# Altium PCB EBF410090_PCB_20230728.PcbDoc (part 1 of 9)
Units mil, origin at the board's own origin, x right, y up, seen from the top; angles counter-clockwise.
Board outline 5393.69 x 3858.26 mil, 6 copper layers (TOP, GND02, ART03, ART04, PWR05, BOTTOM), stack 47.2 mil thick; 570 components, 437 nets, 2015 pads, 1260 vias.
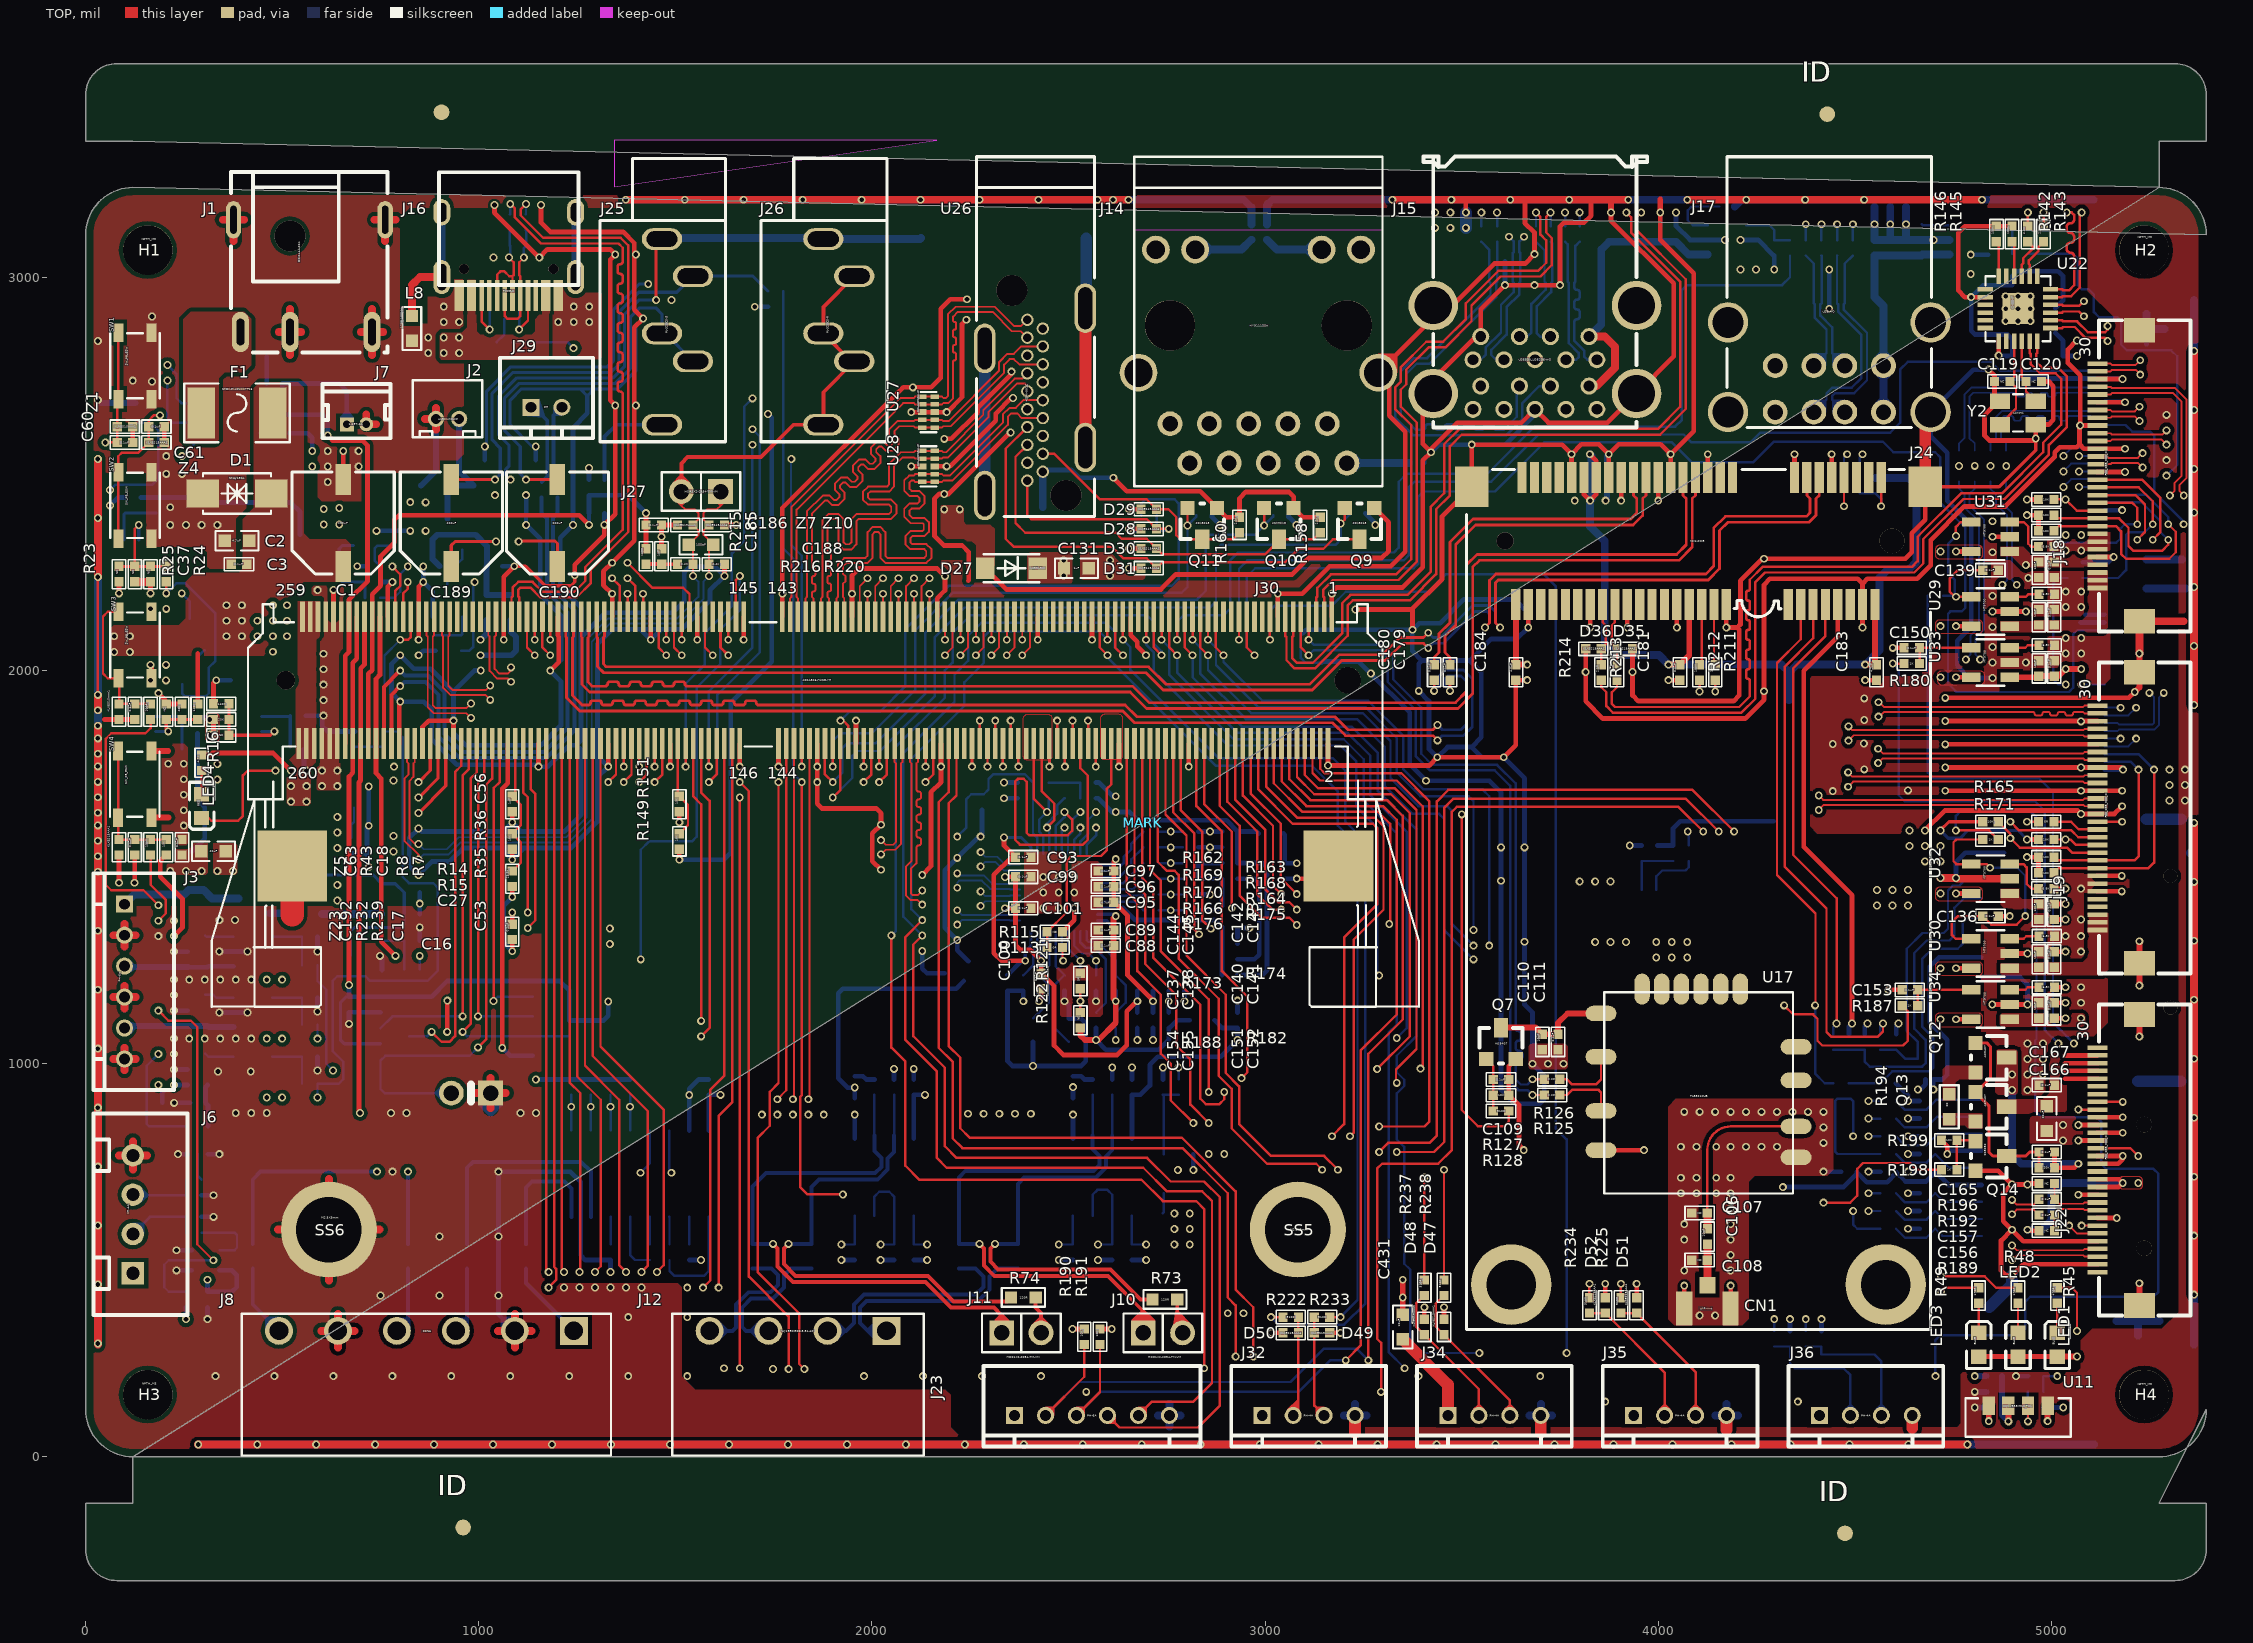
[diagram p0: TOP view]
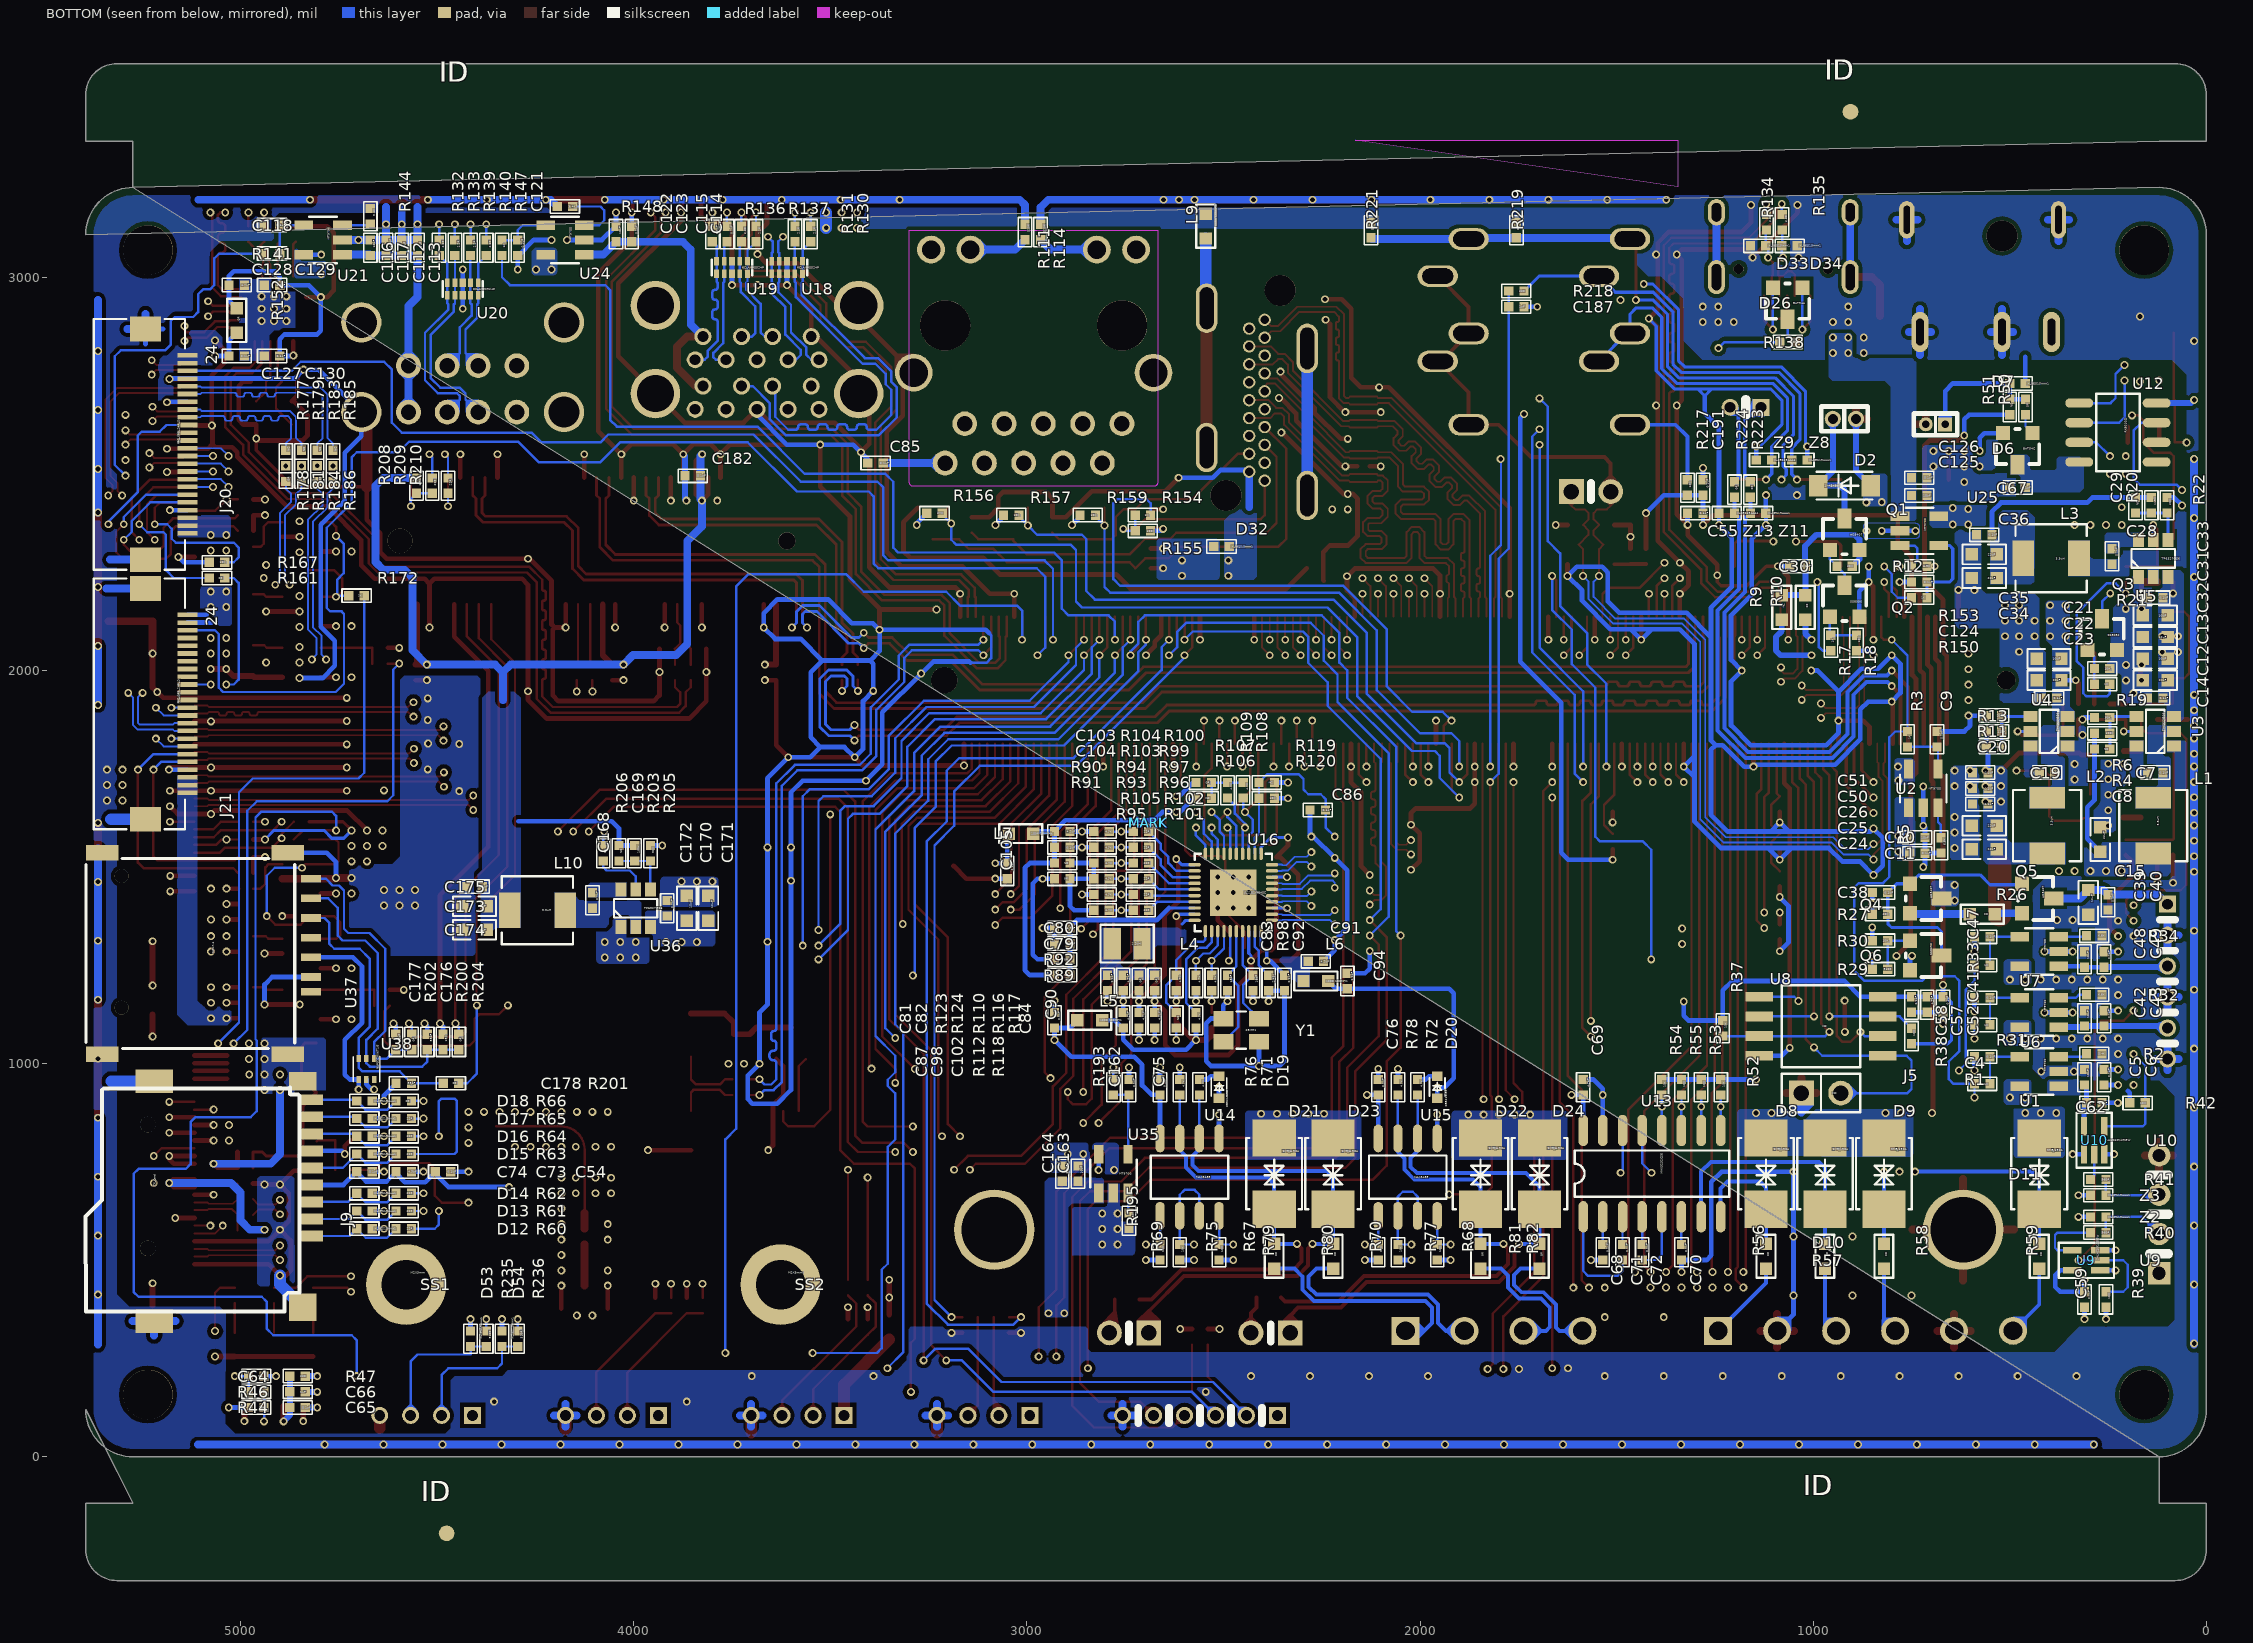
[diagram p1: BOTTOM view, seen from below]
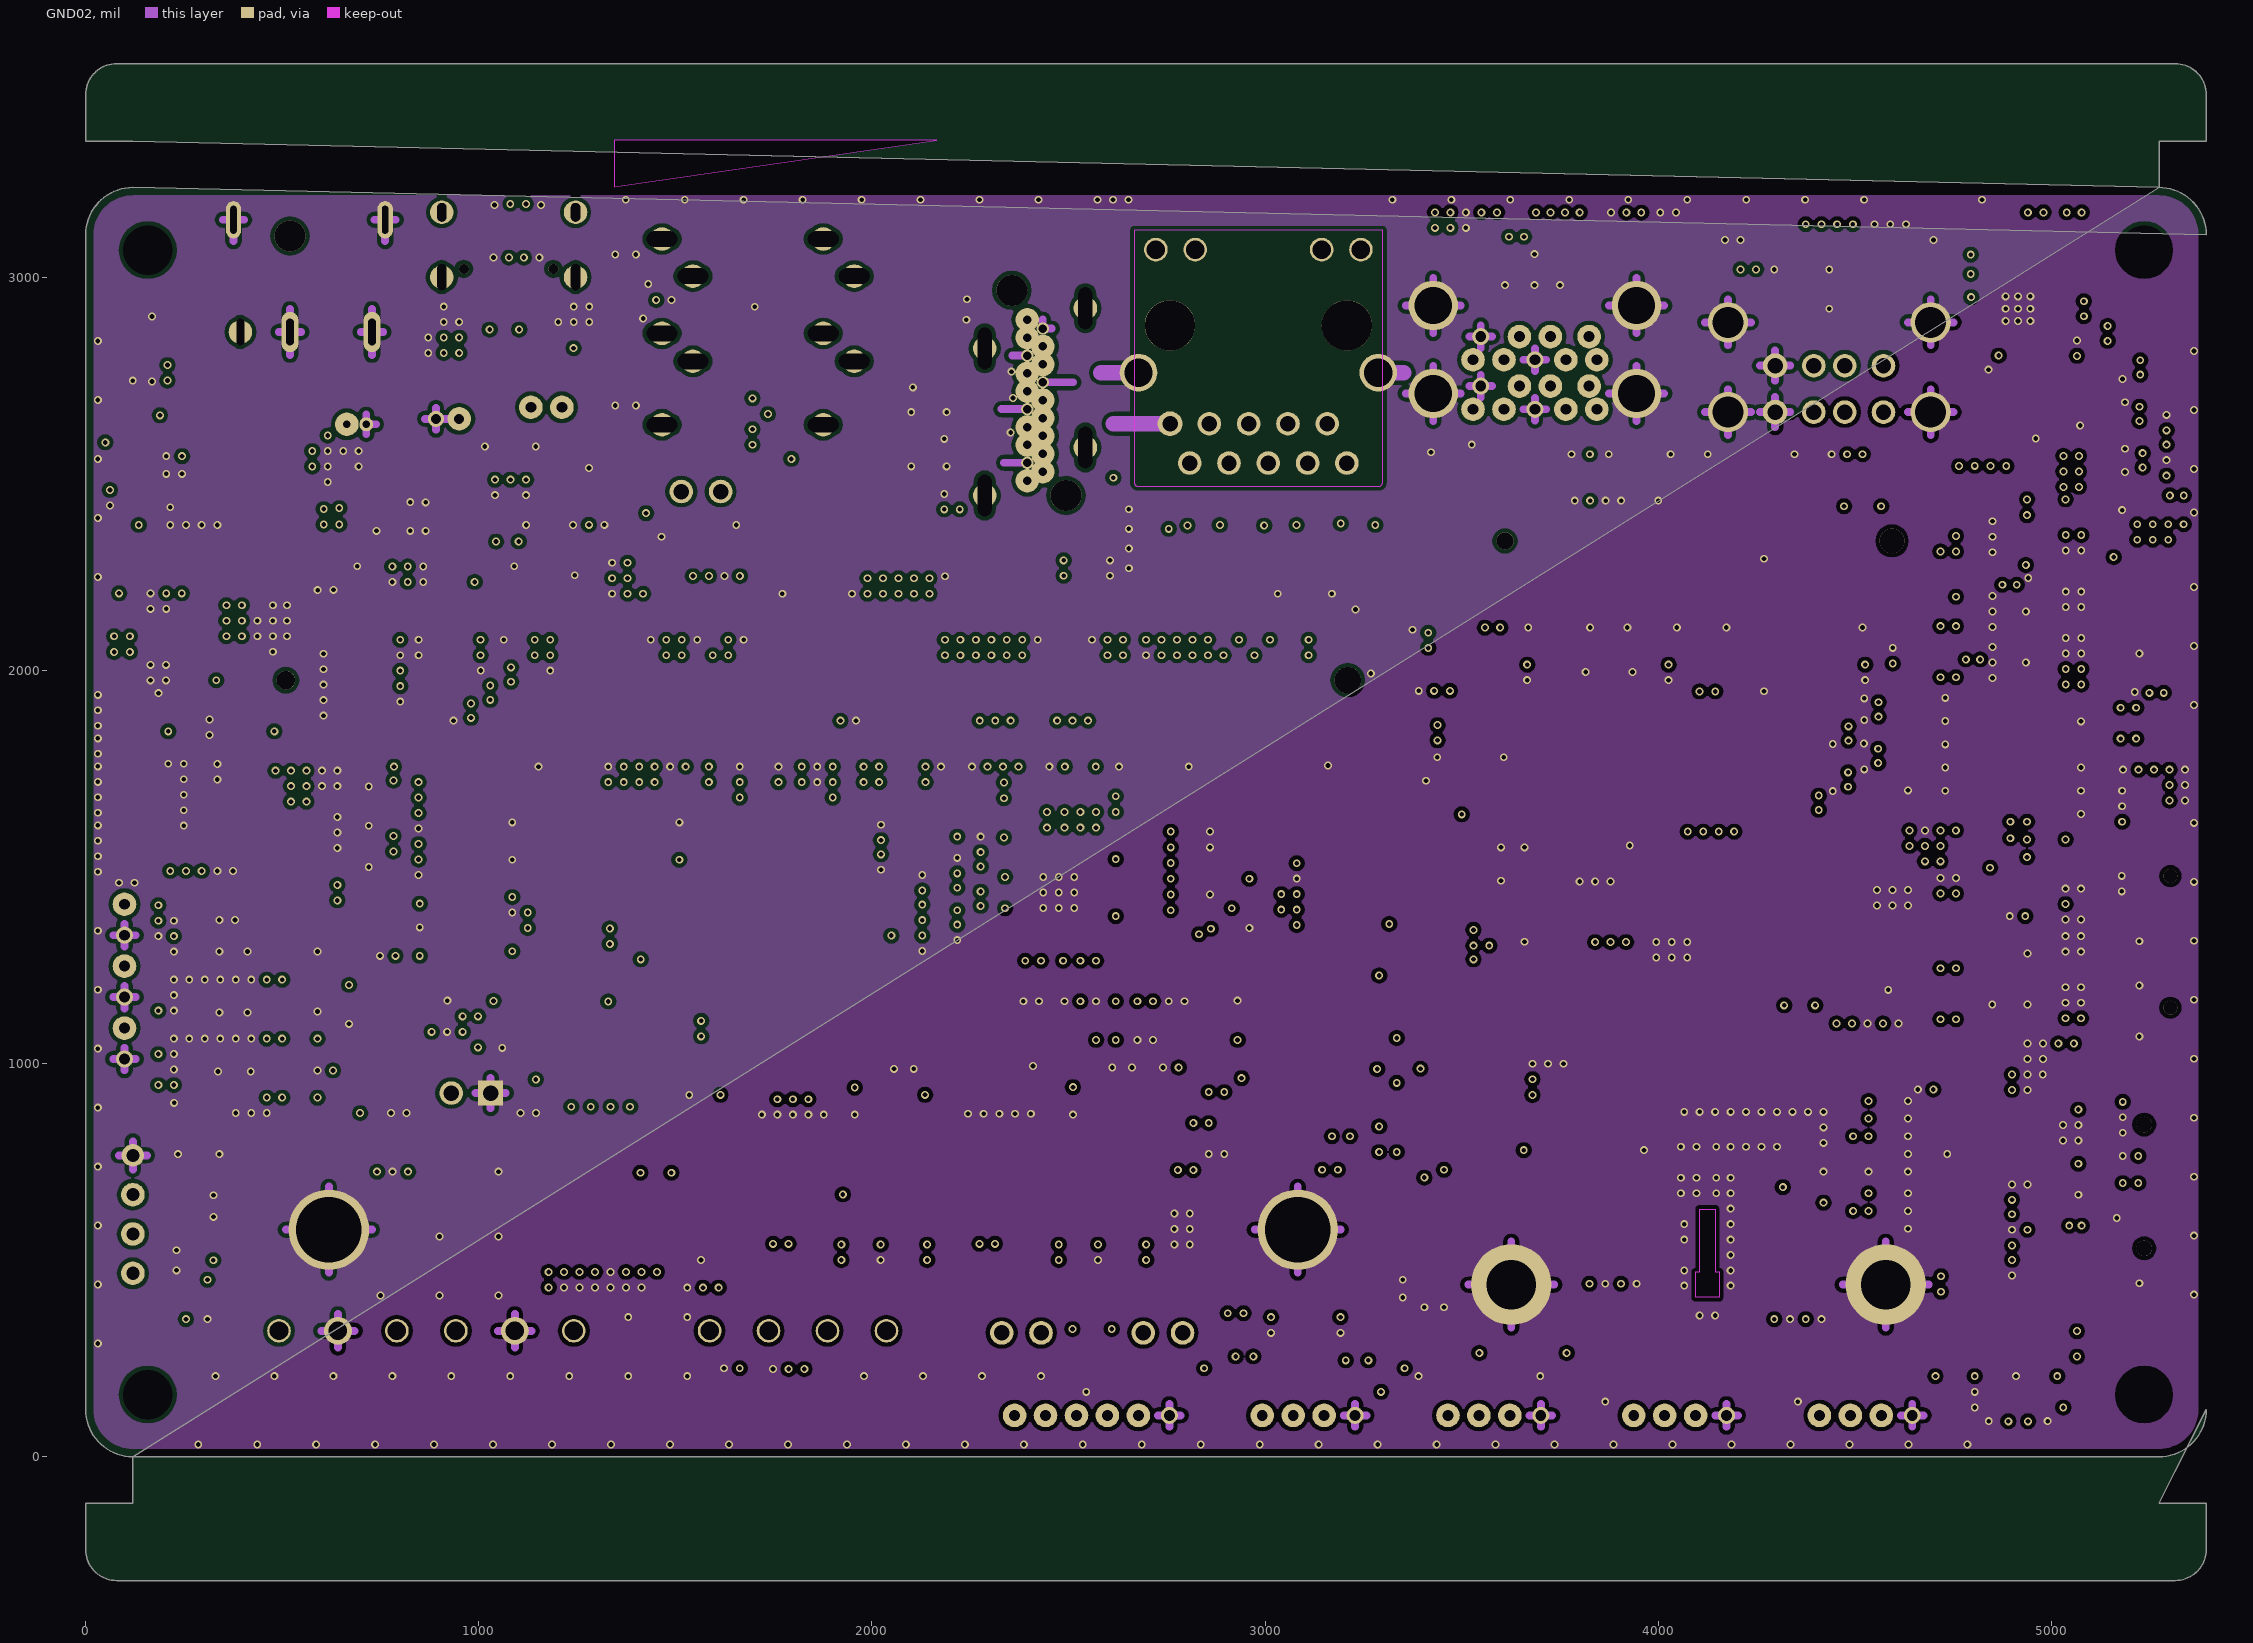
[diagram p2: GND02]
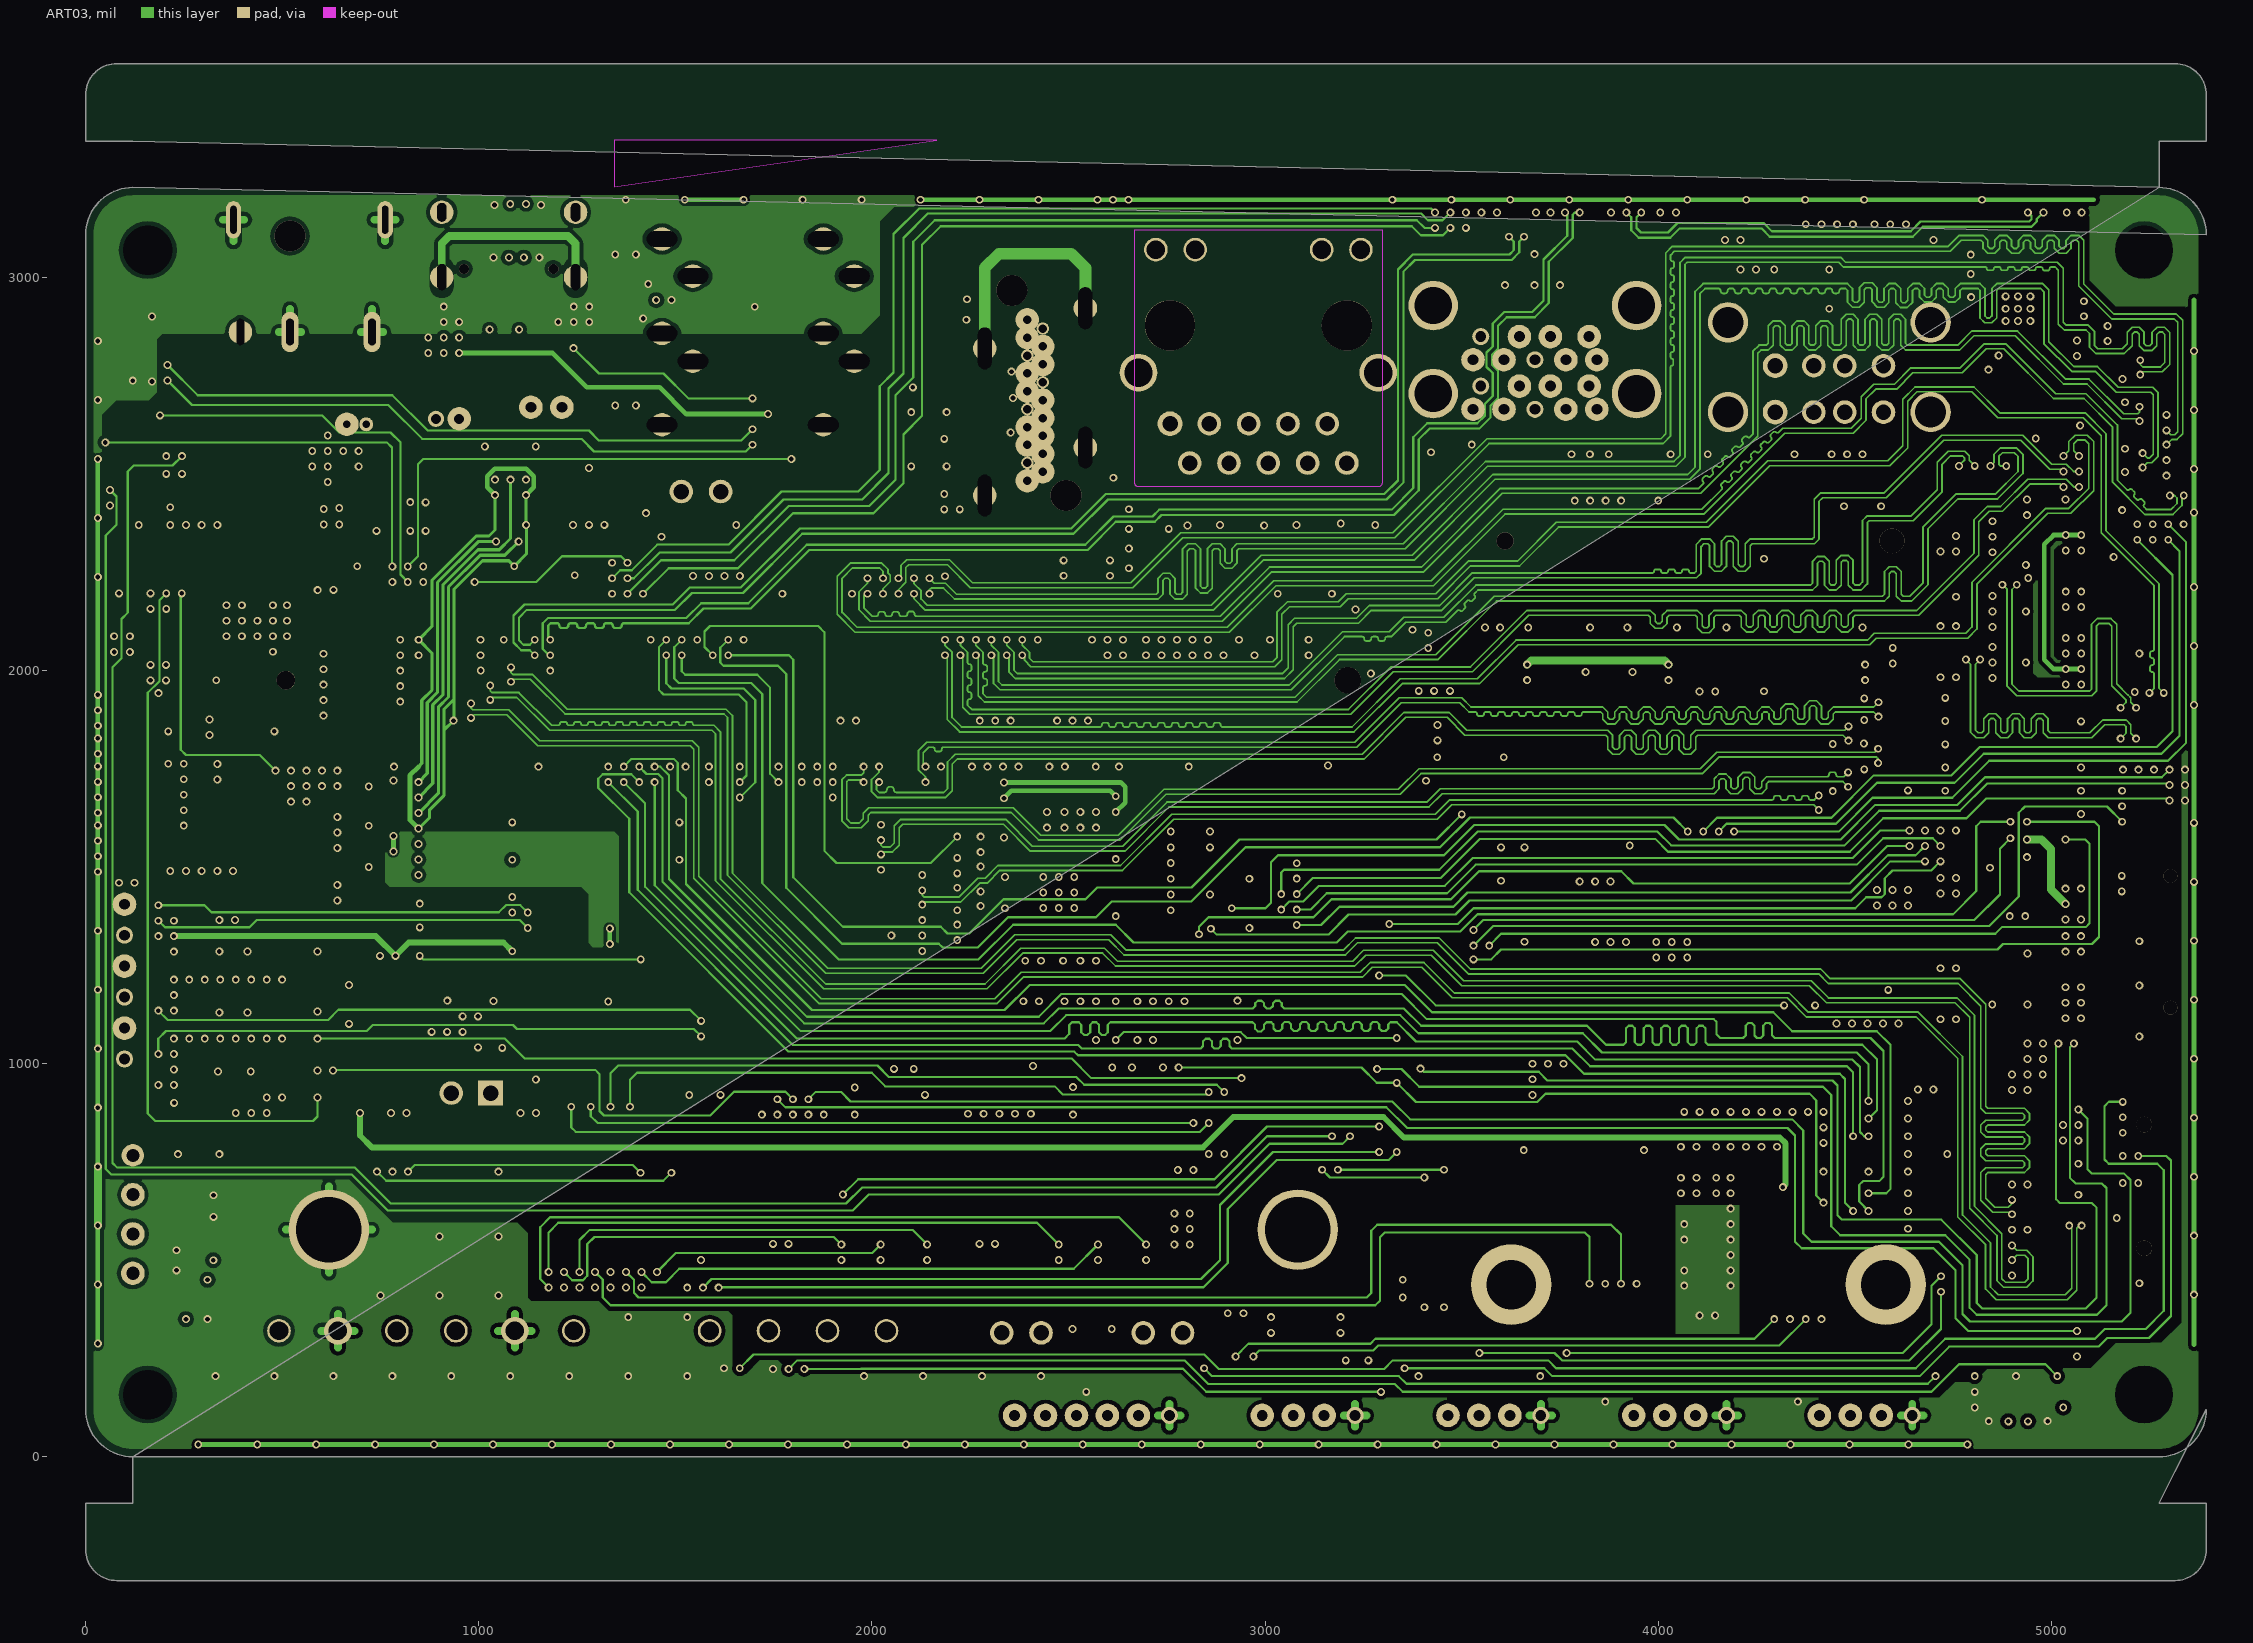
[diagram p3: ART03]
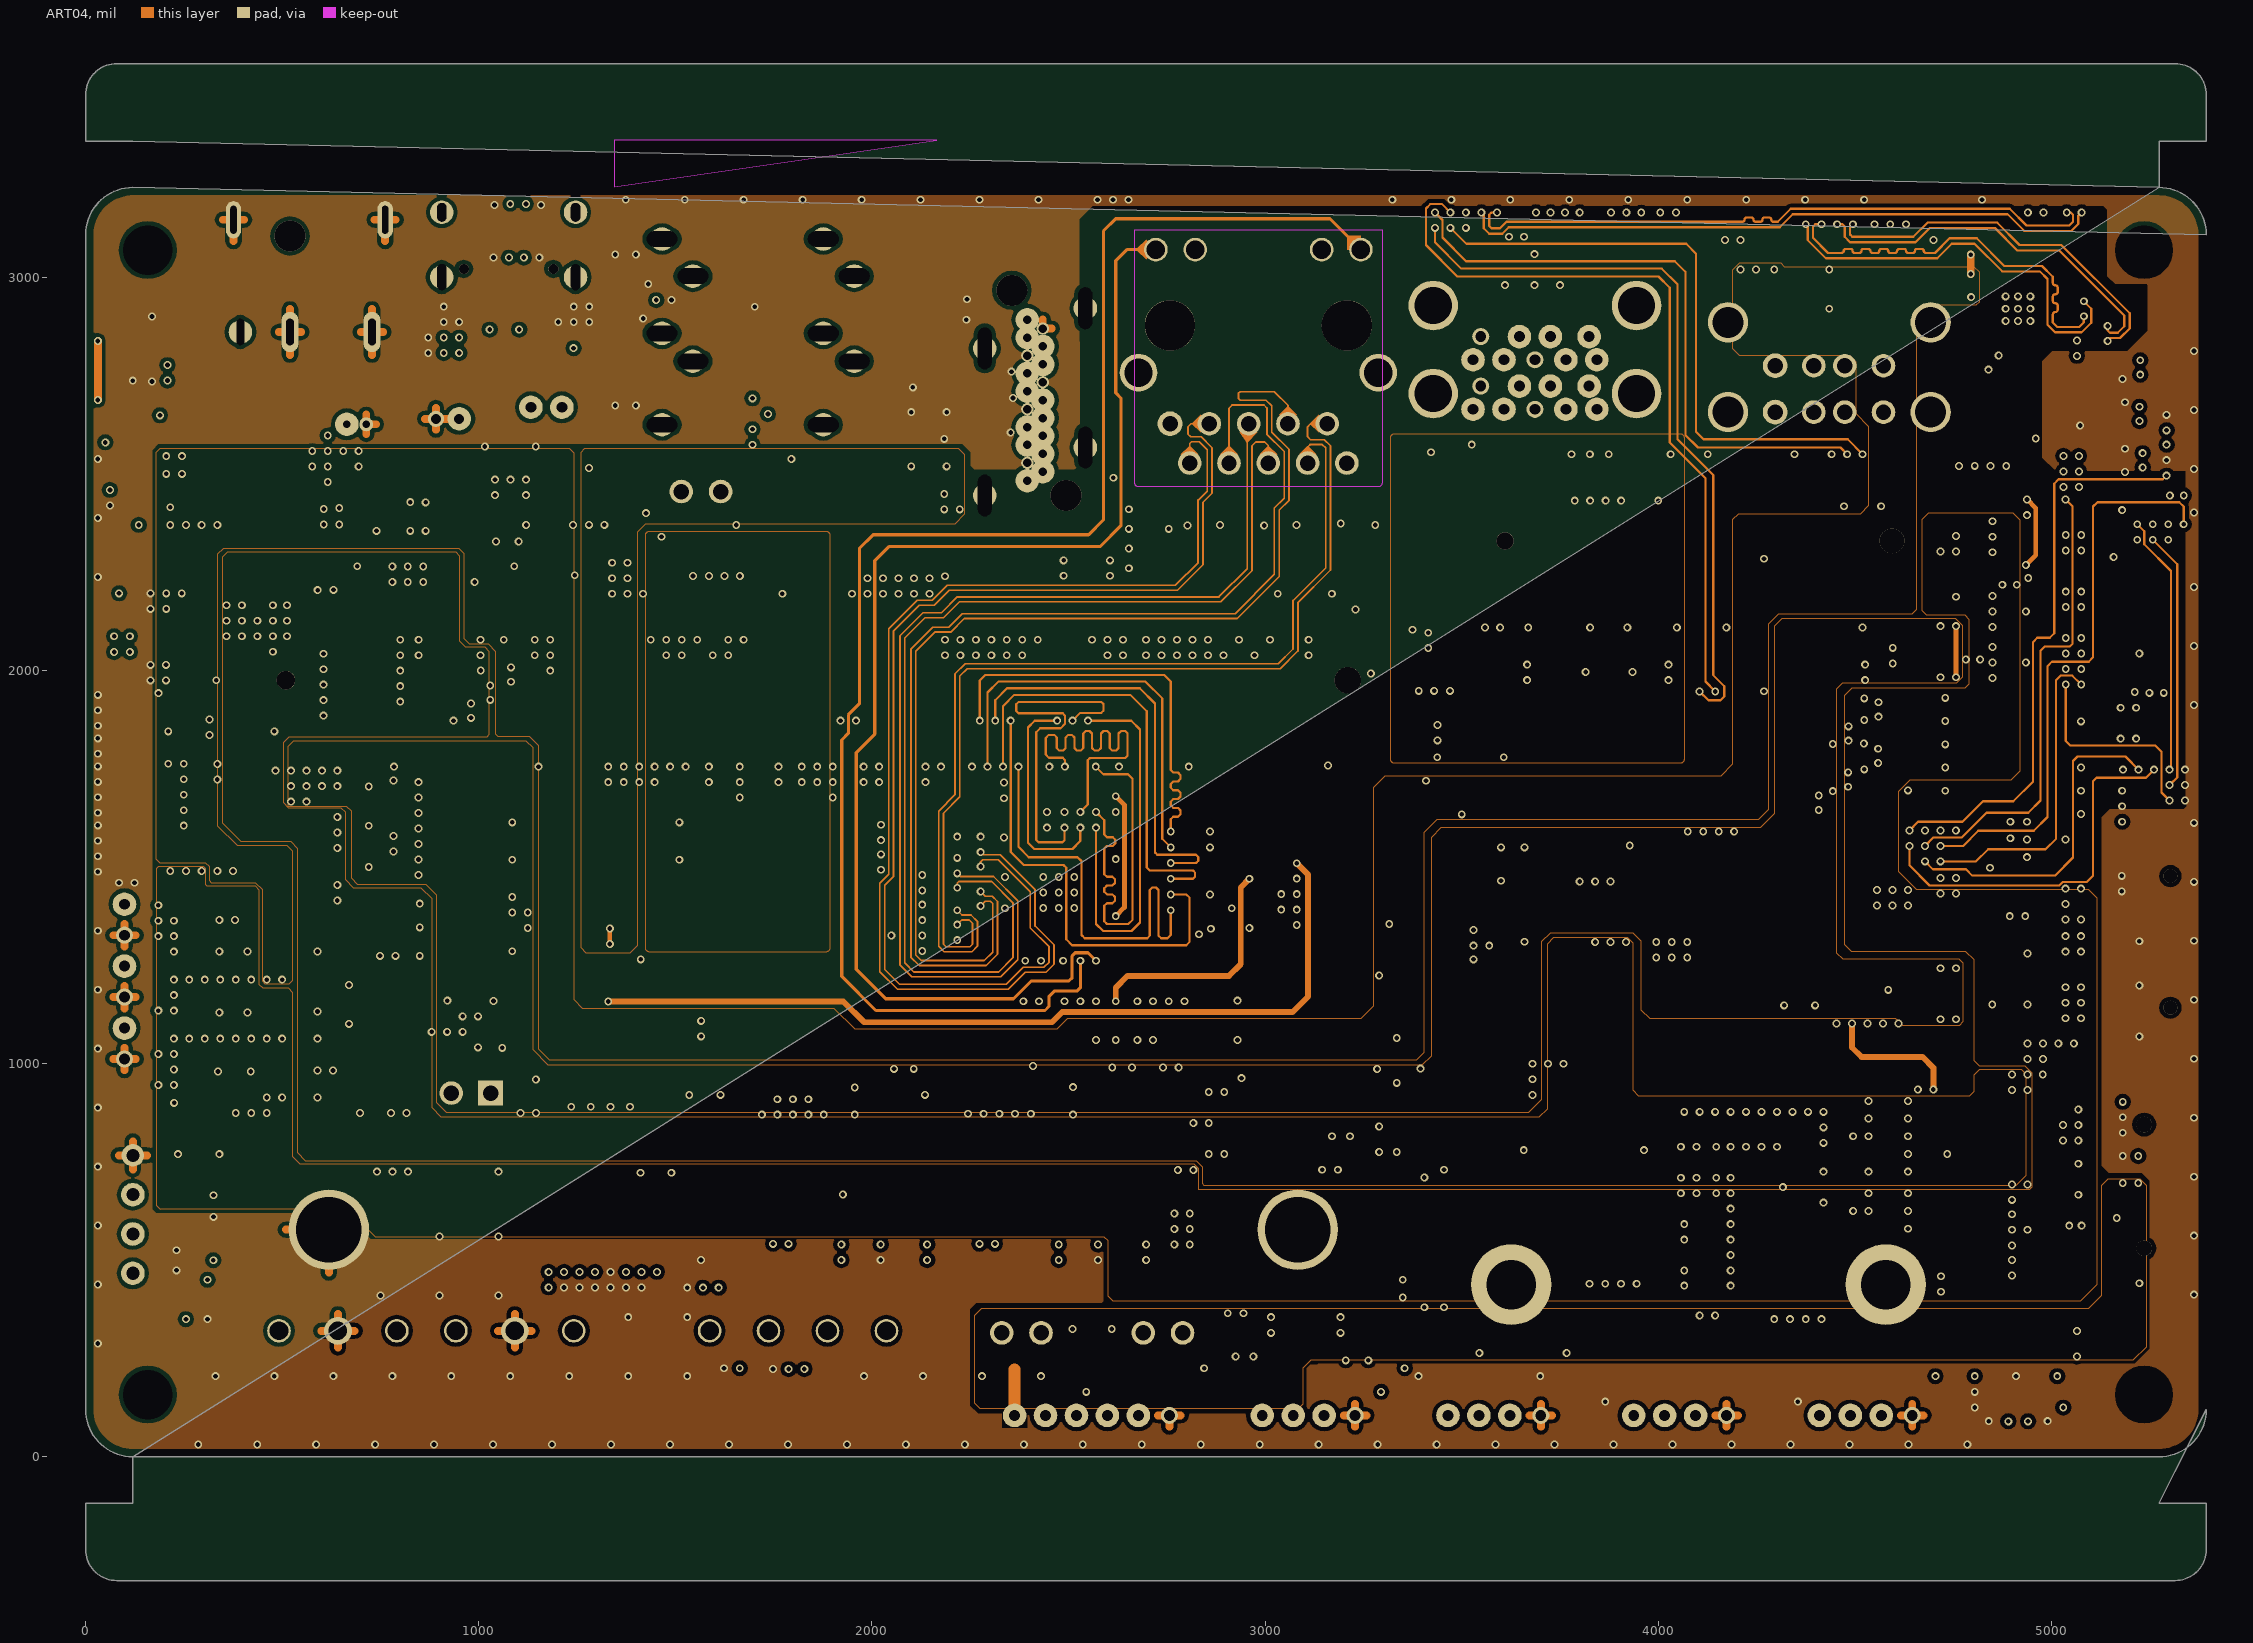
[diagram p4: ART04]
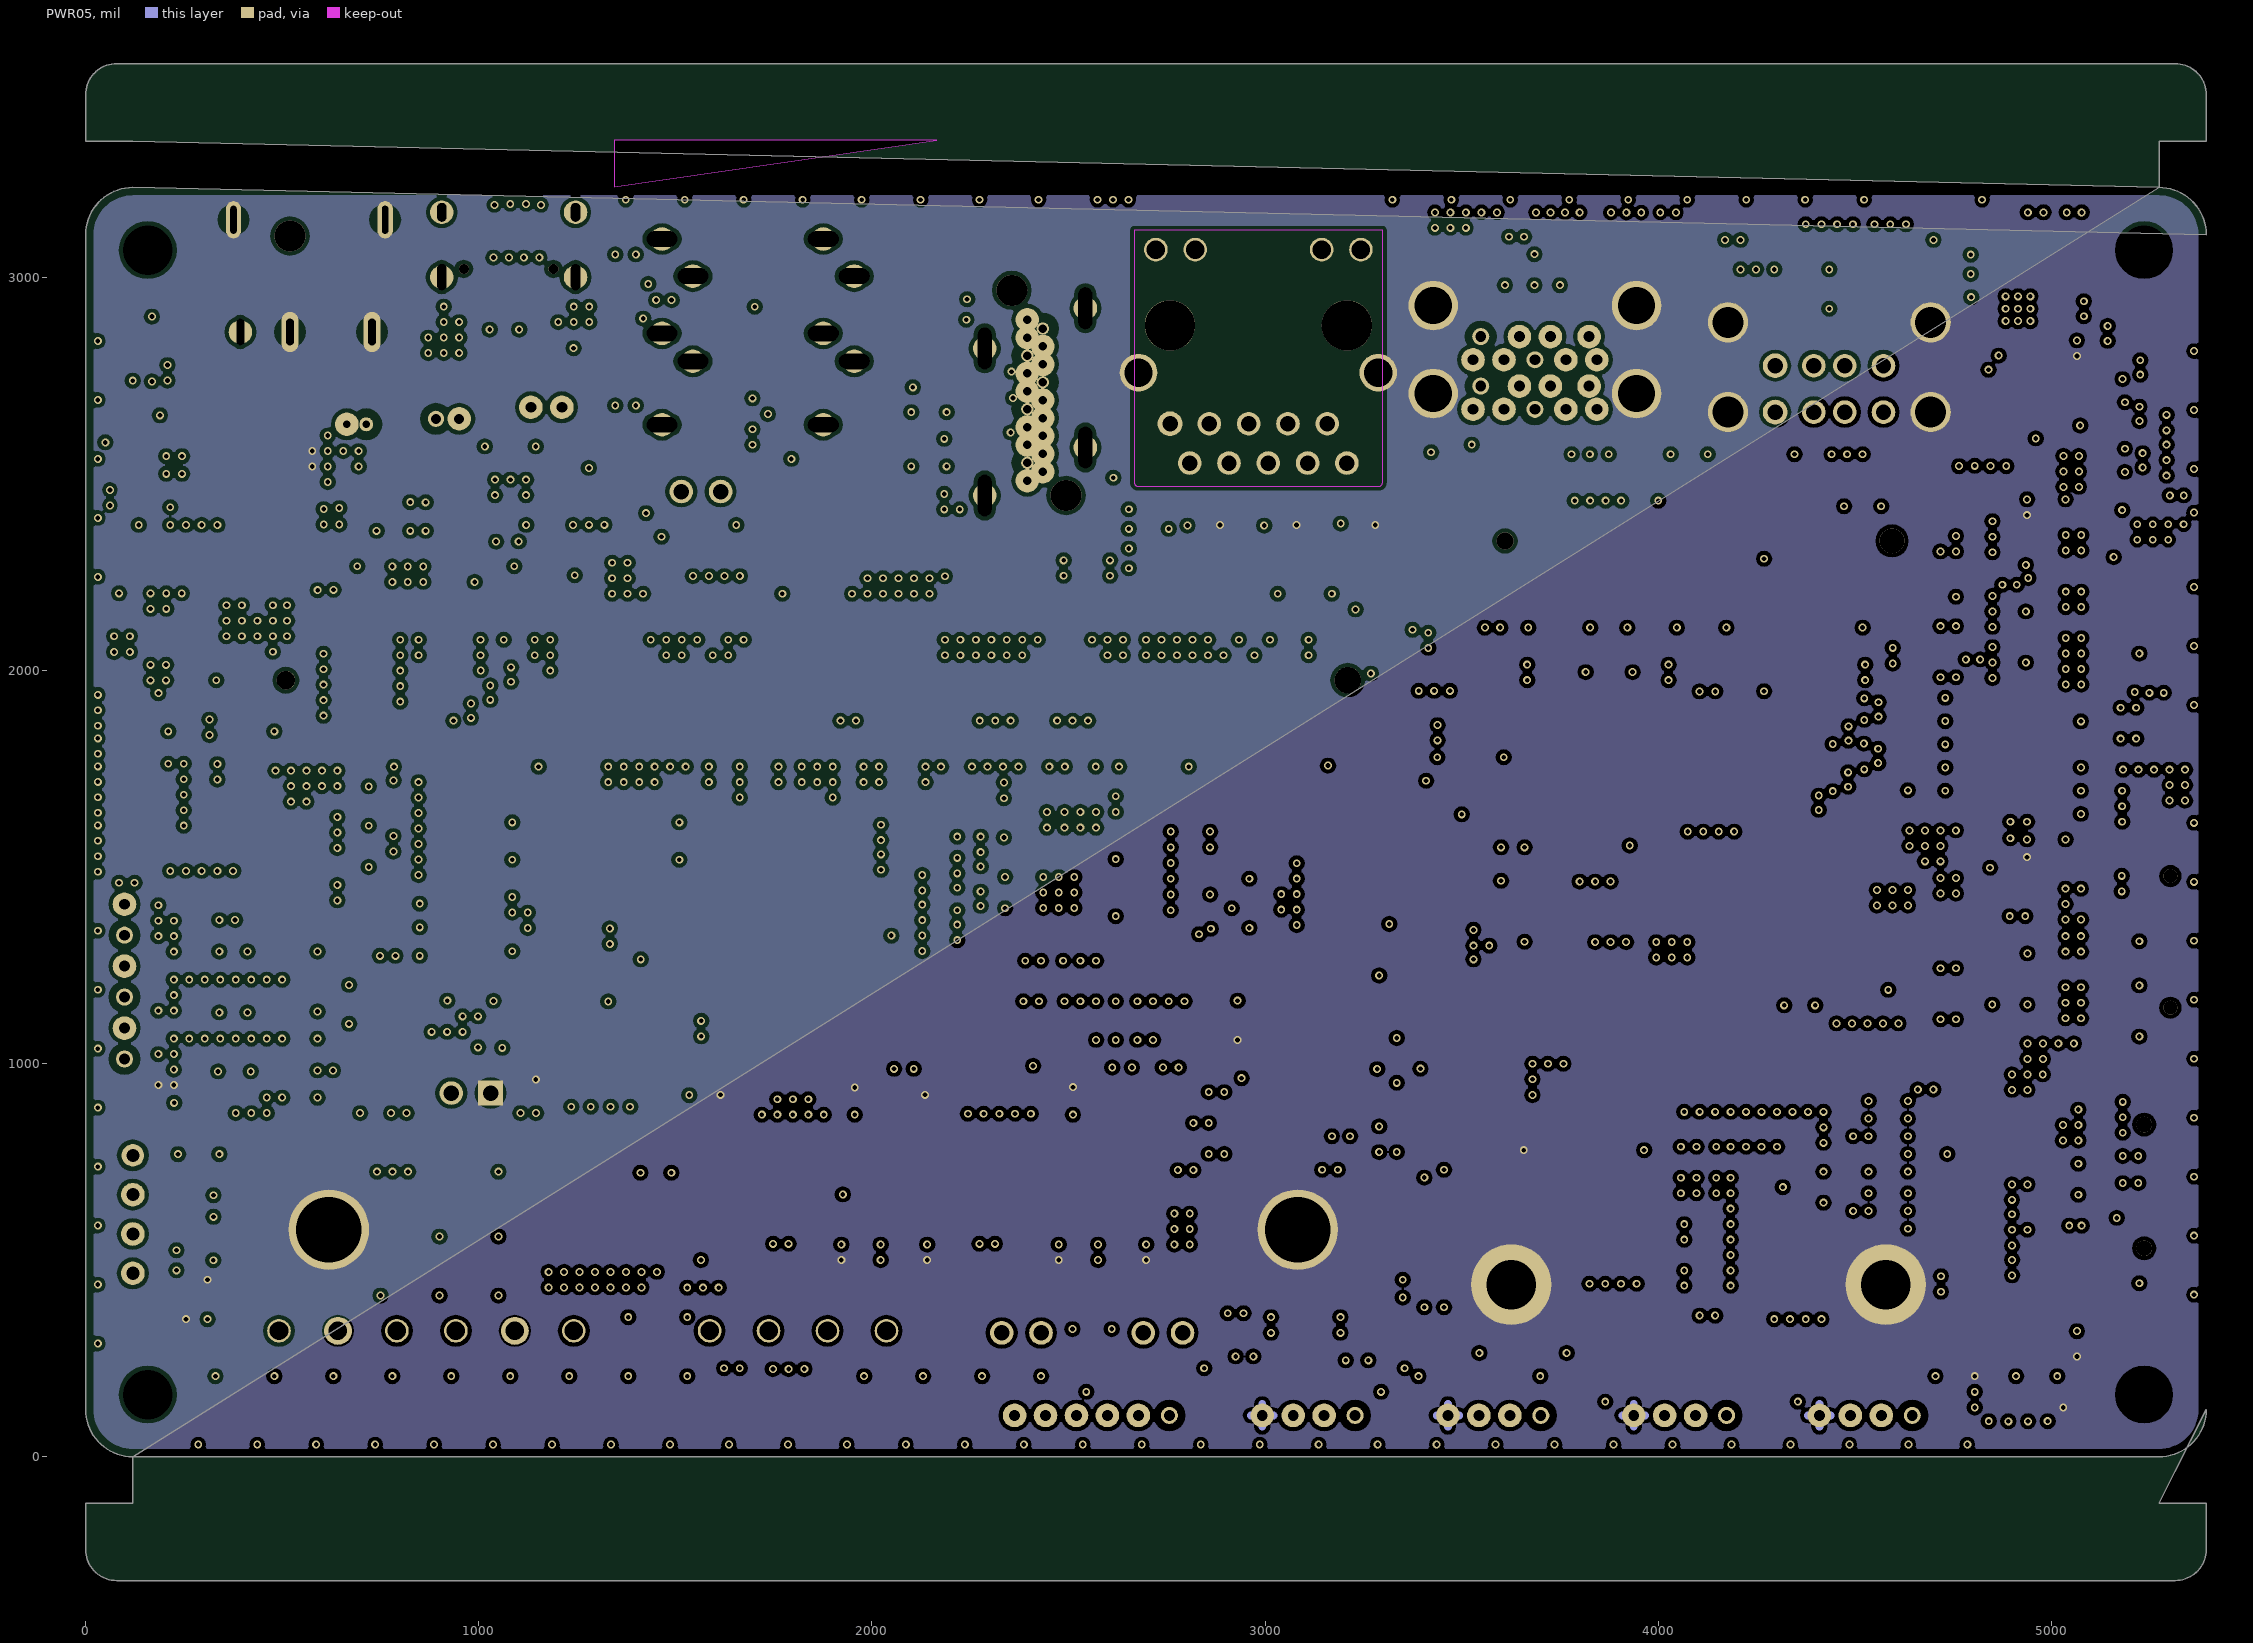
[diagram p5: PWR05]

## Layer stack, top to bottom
Top Solder: solder mask 0.4, Solder Resist, Dk 3.5
TOP: signal copper 1.2
Dielectric 1: core 8, FR-4, Dk 4.5
GND02: signal copper 1.2
Dielectric2: core 8, FR-4, Dk 4.5
ART03: signal copper 1.2
Dielectric3: core 8, FR-4, Dk 4.5
ART04: signal copper 1.2
Dielectric4: core 8, FR-4, Dk 4.5
PWR05: signal copper 1.2
Dielectric5: core 8, FR-4, Dk 4.5
BOTTOM: signal copper 1.2
Bottom Solder: solder mask 0.4, Solder Resist, Dk 3.5

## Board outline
5273.69,3228.34 120,3346.45 0,3346.45 0,3464.56 cw(c78.74,3464.56) 5314.95,3543.3 cw(c5314.95,3464.56) 5393.69,3346.45 5273.69,3346.45 5273.69,3228.34 cw(c5273.69,3108.34) 120,3228.34 ccw(c120,3108.34) 0,120 ccw(c120,120) 120,0 5273.69,0 ccw(c5273.69,120) 5273.69,-118.11 5393.69,-118.11 5393.69,-236.22 cw(c5314.95,-236.22) 78.74,-314.96 cw(c78.74,-236.22) 0,-118.11 120,-118.11 120,0
cut-out: 2165,3348.11 1345,3348.11 1345,3230

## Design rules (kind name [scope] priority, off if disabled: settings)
Clearance [All] p1: gap=10 ignorepadtopadclearanceinfootprint=FALSE except(0: Arc-Hole Track-Hole SMDPad-Hole THPad-Hole Via-Hole Fill-Hole Poly-Hole Region-Hole Text-Hole)
DiffPairsRouting [All] p1: maxlimit=10 minlimit=10 mostfreqgap=10 toplayer_minwidth=15 toplayer_maxwidth=15 toplayer_prefwidth=15 midlayer1_minwidth=15 midlayer1_maxwidth=15 midlayer1_prefwidth=15 midlayer2_minwidth=15 midlayer2_maxwidth=15 midlayer2_prefwidth=15 midlayer3_minwidth=15 midlayer3_maxwidth=15 midlayer3_prefwidth=15 midlayer4_minwidth=15 midlayer4_maxwidth=15 midlayer4_prefwidth=15 bottomlayer_minwidth=15 bottomlayer_maxwidth=15 bottomlayer_prefwidth=15 maxuncoupledlength=500
PlaneConnect [All] p1: planeconnectstyle=Direct reliefexpansion=20 reliefentries=4 reliefconductorwidth=10 reliefairgap=10
PolygonConnect [All] p1: connectstyle=Direct reliefconductorwidth=10 reliefentries=4 polygonreliefangle="90 Angle" airgapwidth=10
RoomDefinition RoomsKeepin1 [All vs False] p1: confinementstyle=ConfineIn formatcopy=TRUE lockcomponents=FALSE outline 5273.69,3188.34 5280.66,3188.04 5287.58,3187.12 5294.4,3185.61 5301.05,3183.52 5307.5,3180.84 5313.69,3177.62 5319.58,3173.87 5325.11,3169.62 5330.26,3164.91 5334.97,3159.76 5339.22,3154.23 5342.97,3148.34 5346.19,3142.15 5348.87,3135.7 5350.96,3129.05 5352.47,3122.23 5353.39,3115.31 5353.69,3108.34 5353.69,120 5353.39,113.03 5352.47,106.11 5350.96,99.29 5348.87,92.64 5346.19,86.19 5342.97,80 5339.22,74.11 5334.97,68.58 5330.26,63.43 5325.11,58.72 5319.58,54.47 5313.69,50.72 5307.5,47.5 5301.05,44.82 5294.4,42.73 5287.58,41.22 5280.66,40.3 5273.69,40 120,40 113.03,40.3 106.11,41.22 99.29,42.73 92.64,44.82 86.19,47.5 80,50.72 74.11,54.47 68.58,58.72 63.43,63.43 58.72,68.58 54.47,74.11 50.72,80 47.5,86.19 44.82,92.64 42.73,99.29 41.22,106.11 40.3,113.03 40,120 40,3108.34 40.3,3115.31 41.22,3122.23 42.73,3129.05 44.82,3135.7 47.5,3142.15 50.72,3148.34 54.47,3154.23 58.72,3159.76 63.43,3164.91 68.58,3169.62 74.11,3173.87 80,3177.62 86.19,3180.84 92.64,3183.52 99.29,3185.61 106.11,3187.12 113.03,3188.04 120,3188.34 5273.69,3188.34
RoomDefinition RoomsKeepin0 [All vs False] p2: confinementstyle=ConfineIn formatcopy=TRUE lockcomponents=FALSE outline 5273.69,3188.34 5280.66,3188.04 5287.58,3187.12 5294.4,3185.61 5301.05,3183.52 5307.5,3180.84 5313.69,3177.62 5319.58,3173.87 5325.11,3169.62 5330.26,3164.91 5334.97,3159.76 5339.22,3154.23 5342.97,3148.34 5346.19,3142.15 5348.87,3135.7 5350.96,3129.05 5352.47,3122.23 5353.39,3115.31 5353.69,3108.34 5353.69,120 5353.39,113.03 5352.47,106.11 5350.96,99.29 5348.87,92.64 5346.19,86.19 5342.97,80 5339.22,74.11 5334.97,68.58 5330.26,63.43 5325.11,58.72 5319.58,54.47 5313.69,50.72 5307.5,47.5 5301.05,44.82 5294.4,42.73 5287.58,41.22 5280.66,40.3 5273.69,40 120,40 113.03,40.3 106.11,41.22 99.29,42.73 92.64,44.82 86.19,47.5 80,50.72 74.11,54.47 68.58,58.72 63.43,63.43 58.72,68.58 54.47,74.11 50.72,80 47.5,86.19 44.82,92.64 42.73,99.29 41.22,106.11 40.3,113.03 40,120 40,3108.34 40.3,3115.31 41.22,3122.23 42.73,3129.05 44.82,3135.7 47.5,3142.15 50.72,3148.34 54.47,3154.23 58.72,3159.76 63.43,3164.91 68.58,3169.62 74.11,3173.87 80,3177.62 86.19,3180.84 92.64,3183.52 99.29,3185.61 106.11,3187.12 113.03,3188.04 120,3188.34 5273.69,3188.34
RoutingVias [All] p1: holewidth=28 width=50 viastyle="Through Hole" minholewidth=28 minwidth=50 maxholewidth=28 maxwidth=50
SolderMaskExpansion [All] p1: expansion=4 istentingtop=FALSE
Width [All] p1: maxlimit=10 minlimit=10 preferedwidth=10 impedanceprofiledriven=TRUE minimp=14.100000 maximp=52.430000 favimp=8.590000
28 further rules are at their usual default settings.

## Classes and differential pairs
net class PWR_G: GND
differential pair DIFF_SS_TX: +USB3_HOST1_SSTXN -USB3_HOST1_SSTXP
differential pair DIFF_USB3_HOST1_SSRX: +USB3_HOST1_SSRXN -USB3_HOST1_SSRXP
differential pair DIFFPAIR5: +USB3_HOST1_DM -USB3_HOST1_DP
differential pair DIFF_USB2_HOST3_D: +USB2_HOST3_DM -USB2_HOST3_DP
differential pair DIFFPAIR6: +USB2_HOST2_DM -USB2_HOST2_DP
differential pair DIFFPAIR3: +USB_OTG0_DM -USB_OTG0_DP
differential pair DIFF_SS_TX: +SS_TXP -USB3_HOST1_SSTXN
differential pair DIFF_SS_TX: +SS_TXN -SS_TXP
differential pair DIFF_CIE20_TXP: +PE_TXN -PE_TXP
differential pair DIFF_CIE20_TXP: +PCIE20_TXP -PE_TXN
differential pair DIFF_CIE20_TXP: +PCIE20_TXN -PCIE20_TXP
differential pair DIFF_CIE20_RXP: +PCIE20_RXN -PCIE20_RXP
differential pair DIFF_CIE20_REFCLKP: +PCIE20_REFCLKN -PCIE20_REFCLKP
differential pair DIFFPAIR3: +OTG0_DP -USB_OTG0_DM
differential pair DIFFPAIR3: +OTG0_DM -OTG0_DP
differential pair DIFFPAIR6: +N18057335 -USB2_HOST2_DM
differential pair DIFFPAIR6: +N18057325 -N18057335
differential pair DIFF_USB2_HOST3_D: +N17770942 -USB2_HOST3_DM
differential pair DIFF_USB2_HOST3_D: +N17770939 -N17770942
differential pair DIFF_MII_DSI_TX1_D3P: +MIPI_DSI_TX1_D3N -MIPI_DSI_TX1_D3P
differential pair DIFF_MII_DSI_TX1_D2P: +MIPI_DSI_TX1_D2N -MIPI_DSI_TX1_D2P
differential pair DIFF_MII_DSI_TX1_D1P: +MIPI_DSI_TX1_D1N -MIPI_DSI_TX1_D1P
differential pair DIFF_MII_DSI_TX1_D0P: +MIPI_DSI_TX1_D0N -MIPI_DSI_TX1_D0P
differential pair DIFF_MII_DSI_TX1_CLKP: +MIPI_DSI_TX1_CLKN -MIPI_DSI_TX1_CLKP
differential pair DIFF_MII_DSI_TX0_D3P: +MIPI_DSI_TX0_D3N -MIPI_DSI_TX0_D3P
differential pair DIFF_MII_DSI_TX0_D2P: +MIPI_DSI_TX0_D2N -MIPI_DSI_TX0_D2P
differential pair DIFF_MII_DSI_TX0_D1P: +MIPI_DSI_TX0_D1N -MIPI_DSI_TX0_D1P
differential pair DIFF_MII_DSI_TX0_D0P: +MIPI_DSI_TX0_D0N -MIPI_DSI_TX0_D0P
differential pair DIFF_MII_DSI_TX0_CLKP: +MIPI_DSI_TX0_CLKN -MIPI_DSI_TX0_CLKP
differential pair DIFF_CSI_RX_D3_S0: +MIPI_CSI_RX_D3N -MIPI_CSI_RX_D3P
differential pair DIFF_CSI_RX_D2_S0: +MIPI_CSI_RX_D2N -MIPI_CSI_RX_D2P
differential pair DIFF_MII_CSI_RX_D1P: +MIPI_CSI_RX_D1N -MIPI_CSI_RX_D1P
differential pair DIFF_MII_CSI_RX_D0P: +MIPI_CSI_RX_D0N -MIPI_CSI_RX_D0P
differential pair DIFF_MII_CSI_RX_CLK1P: +MIPI_CSI_RX_CLK1N -MIPI_CSI_RX_CLK1P
differential pair DIFF_MII_CSI_RX_CLK0P: +MIPI_CSI_RX_CLK0N -MIPI_CSI_RX_CLK0P
differential pair DIFFPAIR7: +MIC_INN -MIC_INP
differential pair DIFF_MDI3_PHY: +MDIN3_PHY -MDIP3_PHY
differential pair DIFF_MDI2_PHY: +MDIN2_PHY -MDIP2_PHY
differential pair DIFF_MDI1_PHY: +MDIN1_PHY -MDIP1_PHY
differential pair DIFF_MDI0_PHY: +MDIN0_PHY -MDIP0_PHY
differential pair DIFFPAIR2: +HUB_DM4 -HUB_DP4
differential pair DIFFPAIR1: +HUB_DM3 -HUB_DP3
differential pair DIFFPAIR0: +HUB_DM2 -HUB_DP2
differential pair DIFFPAIR4: +HUB_DM1 -HUB_DP1
differential pair DIFFPAIR5: +HOST1_DP -USB3_HOST1_DM
differential pair DIFFPAIR5: +HOST1_DM -HOST1_DP
differential pair DIFF_HDMI_TXCLK_PORT: +HDMI_TXCLKN_PORT -HDMI_TXCLKP_PORT
differential pair DIFF_HDMI_TX2_PORT: +HDMI_TX2N_PORT -HDMI_TX2P_PORT
differential pair DIFF_HDMI_TX1_PORT: +HDMI_TX1N_PORT -HDMI_TX1P_PORT
differential pair DIFF_HDMI_TX0_PORT: +HDMI_TX0N_PORT -HDMI_TX0P_PORT
differential pair DIFF_ED_TX_D1P: +EDP_TX_D1N -EDP_TX_D1P
differential pair DIFF_ED_TX_D0P: +EDP_TX_D0N -EDP_TX_D0P
differential pair DIFF_ED_TX_AUXP: +EDP_TX_AUXN -EDP_TX_AUXP
differential pair DIFF_ED_AUXP: +EDP_AUXN -EDP_AUXP
differential pair DIFFPAIR2: +DP4 -HUB_DM4
differential pair DIFFPAIR2: +DM4 -DP4
differential pair DIFF_CSI_RX_D3_S0: +CSI_RX_D3P_S1 -MIPI_CSI_RX_D3N
differential pair DIFF_CSI_RX_D3_S0: +CSI_RX_D3P_S0 -CSI_RX_D3P_S1
differential pair DIFF_CSI_RX_D3_S0: +CSI_RX_D3N_S1 -CSI_RX_D3P_S0
differential pair DIFF_CSI_RX_D3_S0: +CSI_RX_D3N_S0 -CSI_RX_D3N_S1
differential pair DIFF_CSI_RX_D2_S0: +CSI_RX_D2P_S1 -MIPI_CSI_RX_D2N
differential pair DIFF_CSI_RX_D2_S0: +CSI_RX_D2P_S0 -CSI_RX_D2P_S1
differential pair DIFF_CSI_RX_D2_S0: +CSI_RX_D2N_S1 -CSI_RX_D2P_S0
differential pair DIFF_CSI_RX_D2_S0: +CSI_RX_D2N_S0 -CSI_RX_D2N_S1
differential pair DIFFPAIR1: +B_DP3 -HUB_DM3
differential pair DIFFPAIR0: +B_DP2 -HUB_DM2
differential pair DIFFPAIR4: +B_DP1 -HUB_DM1
differential pair DIFFPAIR1: +B_DM3 -B_DP3
differential pair DIFFPAIR0: +B_DM2 -B_DP2
differential pair DIFFPAIR4: +B_DM1 -B_DP1

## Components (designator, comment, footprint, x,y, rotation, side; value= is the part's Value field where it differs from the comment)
C1 "CAP_EC6P3_220UF" EC6P3 655,2375 r180 top
C2 "CAP_NP_C0603_DISCRETE_4.7UF" C0603 385,2330 r180 top
C3 "CAP_NP_C0402_DISCRETE_0.1UF" C0402#1 390,2270 r180 top
C4 "CAP_NP_C0402_DISCRETE_0.1UF" C0402#1 570,1017.4 r0 bottom
C5 "CAP_NP_C0402_DISCRETE_10UF" C0402#1 310,965 r90 bottom
C6 "CAP_NP_C0402_DISCRETE_0.1UF" C0402#1 260,965 r90 bottom
C7 "CAP_NP_C0402_DISCRETE_0.1UF" C0402#2 130,1740 r0 bottom
C8 "CAP_NP_C0402_DISCRETE_NC" C0402#2 265,1800 r0 bottom
C9 "CAP_NP_C0402_DISCRETE_0.1UF" C0402#1 685,1825 r90 bottom
C10 "CAP_NP_C0402_DISCRETE_10UF" C0402#2 735,1575 r0 bottom
C11 "CAP_NP_C0402_DISCRETE_0.1UF" C0402#2 735,1535 r0 bottom
C12 "CAP_NP_C0603_DISCRETE_10UF" C0603 130,1975 r0 bottom
C13 "CAP_NP_C0603_DISCRETE_10UF" C0603 130,2030 r0 bottom
C14 "CAP_NP_C0402_DISCRETE_0.1UF" C0402#1 130,1930 r0 bottom
C15 "CAP_NP_C0603_DISCRETE_22UF" C0603 270,1570 r90 bottom
C16 "CAP_NP_C0603_DISCRETE_22UF" C0603 325,1540 r0 top
C17 "CAP_NP_C0402_DISCRETE_0.1UF" C0402#1 245,1550 r90 top
C18 "CAP_NP_C0402_DISCRETE_NC" C0402#1 205,1895 r270 top
C19 "CAP_NP_C0402_DISCRETE_0.1UF" C0402#2 405,1740 r0 bottom
C20 "CAP_NP_C0402_DISCRETE_NC" C0402#2 540,1805 r0 bottom
C21 "CAP_NP_C0603_DISCRETE_10UF" C0603 400,2030 r0 bottom
C22 "CAP_NP_C0603_DISCRETE_10UF" C0603 400,1975 r0 bottom
C23 "CAP_NP_C0402_DISCRETE_0.1UF" C0402#1 400,1930 r0 bottom
C24 "CAP_NP_C0603_DISCRETE_22UF" C0603 565,1545 r0 bottom
C25 "CAP_NP_C0603_DISCRETE_22UF" C0603 565,1605 r0 bottom
C26 "CAP_NP_C0402_DISCRETE_0.1UF" C0402#1 575,1660 r0 bottom
C27 "CAP_NP_C0402_DISCRETE_NC" C0402#1 345,1835 r0 top
C28 "CAP_NP_C0402_DISCRETE_0.1UF" C0402#1 240,2290 r270 bottom
C29 "CAP_NP_C0402_DISCRETE_NC" C0402#1 180,2420 r270 bottom
C30 "CAP_NP_C0402_DISCRETE_0.1UF" C0402#1 1040,2265 r0 bottom
C31 "CAP_NP_C0603_DISCRETE_10UF" C0603 130,2140 r0 bottom
C32 "CAP_NP_C0603_DISCRETE_10UF" C0603 130,2085 r0 bottom
C33 "CAP_NP_C0402_DISCRETE_0.1UF" C0402#1 130,2185 r0 bottom
C34 "CAP_NP_C0603_DISCRETE_22UF" C0603 565,2235 r0 bottom
C35 "CAP_NP_C0603_DISCRETE_22UF" C0603 565,2295 r0 bottom
C36 "CAP_NP_C0402_DISCRETE_0.1UF" C0402#1 565,2345 r0 bottom
C37 "CAP_NP_C0402_DISCRETE_NC" C0402#1 165,2245 r90 top
C38 "CAP_NP_C0402_DISCRETE_0.1UF" C0402#2 830,1435 r0 bottom
C39 "CAP_NP_C0603_DISCRETE_10UF" C0603 300,1410 r270 bottom
C40 "CAP_NP_C0402_DISCRETE_0.1UF" C0402#1 250,1410 r270 bottom
C41 "CAP_NP_C0402_DISCRETE_0.1UF" C0402#1 570,1167.4 r0 bottom
C42 "CAP_NP_C0402_DISCRETE_10UF" C0402#1 310,1115 r90 bottom
C43 "CAP_NP_C0402_DISCRETE_0.1UF" C0402#1 260,1115 r90 bottom
C47 "CAP_NP_C0402_DISCRETE_0.1UF" C0402#1 570,1322.4 r0 bottom
C48 "CAP_NP_C0402_DISCRETE_10UF" C0402#1 310,1265 r90 bottom
C49 "CAP_NP_C0402_DISCRETE_0.1UF" C0402#1 260,1265 r90 bottom
C50 "CAP_NP_C0402_DISCRETE_0.1UF" C0402#1 575,1700 r0 bottom
C51 "CAP_NP_C0402_DISCRETE_0.1UF" C0402#1 575,1740 r0 bottom
C52 "CAP_NP_C0402_DISCRETE_0.1UF" C0402#1 670,1150 r270 bottom
C53 "CAP_NP_C0402_DISCRETE_0.1UF" C0402#1 1085,1335 r90 top
C54 "CAP_NP_C0402_DISCRETE_0.1UF" C0402#2 4485,725 r0 bottom
C55 "CAP_NP_C0402_DISCRETE_0.1UF" C0402#1 1300,2400 r0 bottom
C56 "CAP_NP_C0402_DISCRETE_1UF" C0402#1 1085,1660 r270 top
C57 "CAP_NP_C0402_DISCRETE_4.7UF" C0402#1 710,1150 r270 bottom
C58 "CAP_NP_C0402_DISCRETE_0.1UF" C0402#1 750,1150 r270 bottom
C59 "CAP_NP_C0402_DISCRETE_0.1UF" C0402#1 310,400 r270 bottom
C60 "CAP_NP_C0402_DISCRETE_0.1UF" C0402#1 100,2580 r0 top
C61 "CAP_NP_C0402_DISCRETE_0.1UF" C0402#1 180,2620 r0 top
C62 "CAP_NP_C0402_DISCRETE_0.1UF" C0402#2 285,900 r0 bottom
C63 "CAP_NP_C0402_DISCRETE_0.1UF" C0402#1 125,1895 r270 top
C64 "CAP_NP_C0402_DISCRETE_NC" C0402#2 4960,205 r0 bottom
C65 "CAP_NP_C0402_DISCRETE_0.1UF" C0402#2 4855,125 r0 bottom
C66 "CAP_NP_C0402_DISCRETE_1UF" C0402#2 4855,165 r0 bottom
C67 "CAP_NP_C0402_DISCRETE_0.1UF" C0402#1 480,2465 r0 bottom
C68 "CAP_NP_C0402_DISCRETE_0.1UF" C0402#1 1535.2,520 r270 bottom
C69 "CAP_NP_C0402_DISCRETE_4.7UF" C0402#1 1585,940 r90 bottom
C70 "CAP_NP_C0402_DISCRETE_0.1UF" C0402#1 1335,520 r270 bottom
C71 "CAP_NP_C0402_DISCRETE_0.1UF" C0402#1 1485,520 r270 bottom
C72 "CAP_NP_C0402_DISCRETE_0.1UF" C0402#1 1435,520 r90 bottom
C73 "CAP_NP_C0402_DISCRETE_4.7UF" C0402#2 4585,725 r0 bottom
C74 "CAP_NP_C0402_DISCRETE_0.1UF" C0402#2 4685,725 r0 bottom
C75 "CAP_NP_C0402_DISCRETE_0.1UF" C0402#1 2661.22,940 r90 bottom
C76 "CAP_NP_C0402_DISCRETE_0.1UF" C0402#1 2106.22,940 r90 bottom
C79 "CAP_NP_C0402_DISCRETE_0.1UF" C0402#1 2910,1305 r0 bottom
C80 "CAP_NP_C0402_DISCRETE_4.7UF" C0402#1 2910,1345 r0 bottom
C81 "CAP_NP_C0402_DISCRETE_0.1UF" C0402#1 2795,1205 r270 bottom
C82 "CAP_NP_C0402_DISCRETE_4.7UF" C0402#1 2755,1205 r270 bottom
C83 "CAP_NP_C0402_DISCRETE_18PF" C0402#1 2425,1205 r270 bottom
C84 "CAP_NP_C0402_DISCRETE_18PF" C0402#1 2490,1205 r270 bottom
C85 "CAP_NP_C0402_DISCRETE_0.1UF" C0402#1 3385,2527.52 r0 bottom
C86 "CAP_NP_C0402_DISCRETE_0.1UF" C0402#1 2260,1645 r0 bottom
C87 "CAP_NP_C0402_DISCRETE_4.7UF" C0402#1 2755,1110 r90 bottom
C88 "CAP_NP_C0402_DISCRETE_0.1UF" C0402#1 2595,1300 r180 top
C89 "CAP_NP_C0402_DISCRETE_0.1UF" C0402#1 2595,1340 r180 top
C90 "CAP_NP_C0402_DISCRETE_0.1UF" C0402#1 2930,1110 r90 bottom
C91 "CAP_NP_C0402_DISCRETE_4.7UF" C0402#2 2265,1260 r0 bottom
C92 "CAP_NP_C0402_DISCRETE_0.1UF" C0402#1 2345,1205 r270 bottom
C93 "CAP_NP_C0402_DISCRETE_0.1UF" C0402#1 2385,1525 r0 top
C94 "CAP_NP_C0402_DISCRETE_0.1UF" C0402#1 2185,1210 r90 bottom
C95 "CAP_NP_C0402_DISCRETE_4.7UF" C0402#1 2595,1410 r180 top
C96 "CAP_NP_C0402_DISCRETE_0.1UF" C0402#1 2595,1450 r180 top
C97 "CAP_NP_C0402_DISCRETE_0.1UF" C0402#1 2595,1490 r180 top
C98 "CAP_NP_C0402_DISCRETE_4.7UF" C0402#1 2715,1110 r270 bottom
C99 "CAP_NP_C0402_DISCRETE_0.1UF" C0402#1 2385,1475 r0 top
C100 "CAP_NP_C0402_DISCRETE_0.1UF" C0402#1 2430,1210 r270 top
C101 "CAP_NP_C0402_DISCRETE_0.1UF" C0402#1 2385,1395 r0 top
C102 "CAP_NP_C0402_DISCRETE_4.7UF" C0402#1 2675,1110 r270 bottom
C103 "CAP_NP_C0402_DISCRETE_4.7UF" C0402#2 2910,1590 r0 bottom
C104 "CAP_NP_C0402_DISCRETE_0.1UF" C0402#2 2910,1550 r0 bottom
C105 "CAP_NP_C0402_DISCRETE_0.1UF" C0402#1 3050,1490 r270 bottom
C106 "CAP_NP_C0402_DISCRETE_10PF" C0402#1 4125,560 r270 top
C107 "CAP_NP_C0402_DISCRETE_NC" C0402#1 4105,620 r180 top
C108 "CAP_NP_C0402_DISCRETE_NC" C0402#1 4105,500 r180 top
C109 "CAP_NP_C0402_DISCRETE_0.1UF" C0402#1 3600,959.44 r180 top
C110 "CAP_NP_C0402_DISCRETE_10UF" C0402#1 3705,1055 r270 top
C111 "CAP_NP_C0402_DISCRETE_0.1UF" C0402#1 3745,1055 r270 top
C112 "CAP_NP_C0402_DISCRETE_1UF" C0402#1 4590,3075 r90 bottom
C113 "CAP_NP_C0402_DISCRETE_1UF" C0402#1 4550,3075 r90 bottom
C114 "CAP_NP_C0402_DISCRETE_0.1UF" C0402#1 3763,3110 r90 bottom
C115 "CAP_NP_C0402_DISCRETE_0.1UF" C0402#1 3800,3110 r90 bottom
C116 "CAP_NP_C0402_DISCRETE_10UF" C0402#1 4670,3075 r90 bottom
C117 "CAP_NP_C0402_DISCRETE_0.1UF" C0402#1 4630,3075 r90 bottom
C118 "CAP_NP_C0402_DISCRETE_0.1UF" C0402#1 4920,3132.4 r0 bottom
C119 "CAP_NP_C0402_DISCRETE_NC" C0402#1 4875,2735 r180 top
C120 "CAP_NP_C0402_DISCRETE_NC" C0402#1 4955,2735 r180 top
C121 "CAP_NP_C0402_DISCRETE_0.1UF" C0402#1 4295,3075 r270 bottom
C122 "CAP_NP_C0402_DISCRETE_10UF" C0402#1 4045,3110 r90 bottom
C123 "CAP_NP_C0402_DISCRETE_0.1UF" C0402#1 4005,3110 r90 bottom
C124 "CAP_NP_C0402_DISCRETE_0.1UF" C0402#1 730,2225 r0 bottom
C125 "CAP_NP_C0402_DISCRETE_10UF" C0402#2 730,2445 r0 bottom
C126 "CAP_NP_C0402_DISCRETE_0.1UF" C0402#2 730,2490 r0 bottom
C127 "CAP_NP_C0402_DISCRETE_0.1UF" C0402#2 5010,2800 r0 bottom
C128 "CAP_NP_C0402_DISCRETE_4.7UF" C0402#2 5010,2980 r0 bottom
C129 "CAP_NP_C0402_DISCRETE_0.1UF" C0402#1 4920,2980 r0 bottom
C130 "CAP_NP_C0402_DISCRETE_0.1UF" C0402#1 4920,2800 r0 bottom
C131 "CAP_NP_C0603_DISCRETE_1UF" C0603 2520,2260 r0 top
C136 "CAP_NP_C0402_DISCRETE_0.1UF" C0402#1 4845,1375 r0 top
C137 "CAP_NP_C0402_DISCRETE_10UF" C0402#1 4968,1265 r90 top
C138 "CAP_NP_C0402_DISCRETE_0.1UF" C0402#1 5007,1265 r90 top
C139 "CAP_NP_C0402_DISCRETE_0.1UF" C0402#1 4845,2255 r0 top
C140 "CAP_NP_C0402_DISCRETE_10UF" C0402#1 4968,2135 r90 top
C141 "CAP_NP_C0402_DISCRETE_0.1UF" C0402#1 5007,2135 r90 top
C142 "CAP_NP_C0402_DISCRETE_10UF" C0402#1 4968,2256 r270 top
C143 "CAP_NP_C0402_DISCRETE_0.1UF" C0402#1 5007,2256 r270 top
C144 "CAP_NP_C0402_DISCRETE_10UF" C0402#1 4968,1386 r270 top
C145 "CAP_NP_C0402_DISCRETE_0.1UF" C0402#1 5007,1386 r270 top
C150 "CAP_NP_C0402_DISCRETE_0.1UF" C0402#1 4645,2057.4 r180 top
C151 "CAP_NP_C0402_DISCRETE_10UF" C0402#1 4968,2005 r90 top
C152 "CAP_NP_C0402_DISCRETE_0.1UF" C0402#1 5007,2005 r90 top
C153 "CAP_NP_C0402_DISCRETE_0.1UF" C0402#1 4640,1187.4 r180 top
C154 "CAP_NP_C0402_DISCRETE_10UF" C0402#1 4968,1135 r90 top
C155 "CAP_NP_C0402_DISCRETE_0.1UF" C0402#1 5007,1135 r90 top
C156 "CAP_NP_C0402_DISCRETE_0.1UF" C0402#1 4988,615 r0 top
C157 "CAP_NP_C0402_DISCRETE_0.1UF" C0402#1 4988,655 r0 top
C162 "CAP_NP_C0402_DISCRETE_0.1UF" C0402#1 2740,940 r90 bottom
C163 "CAP_NP_C0402_DISCRETE_10UF" C0402#1 2870,720 r90 bottom
C164 "CAP_NP_C0402_DISCRETE_0.1UF" C0402#1 2910,720 r90 bottom
C165 "CAP_NP_C0402_DISCRETE_0.1UF" C0402#1 4988,775 r180 top
C166 "CAP_NP_C0603_DISCRETE_10UF" C0603 4988,860 r270 top
C167 "CAP_NP_C0402_DISCRETE_0.1UF" C0402#1 4988,945 r180 top
C168 "CAP_NP_C0402_DISCRETE_0.1UF" C0402#1 4105,1415 r270 bottom
C169 "CAP_NP_C0402_DISCRETE_NC" C0402#1 4037.6,1535 r270 bottom
C170 "CAP_NP_C0603_DISCRETE_10UF" C0603 3865,1395 r90 bottom
C171 "CAP_NP_C0603_DISCRETE_10UF" C0603 3810,1395 r90 bottom
C172 "CAP_NP_C0402_DISCRETE_0.1UF" C0402#1 3915,1395 r90 bottom
C173 "CAP_NP_C0603_DISCRETE_22UF" C0603 4405,1400 r0 bottom
C174 "CAP_NP_C0603_DISCRETE_22UF" C0603 4405,1340 r0 bottom
C175 "CAP_NP_C0402_DISCRETE_0.1UF" C0402#1 4405,1450 r0 bottom
C176 "CAP_NP_C0402_DISCRETE_33PF" C0402#1 4525,1055 r90 bottom
C177 "CAP_NP_C0402_DISCRETE_33PF" C0402#1 4605,1055 r90 bottom
C178 "CAP_NP_C0402_DISCRETE_33PF" C0402#1 4585,950 r0 bottom
C179 "CAP_NP_C0402_DISCRETE_0.1UF" C0402#1 3470,1995 r90 top
C180 "CAP_NP_C0402_DISCRETE_0.1UF" C0402#1 3430,1995 r90 top
C181 "CAP_NP_C0402_DISCRETE_0.1UF" C0402#1 4055,1995 r270 top
C182 "CAP_NP_C0402_DISCRETE_0.1UF" C0402#1 3850,2495 r0 bottom
C183 "CAP_NP_C0402_DISCRETE_4.7UF" C0402#1 4555,1995 r270 top
C184 "CAP_NP_C0402_DISCRETE_4.7UF" C0402#1 3637.85,1995 r270 top
C185 "CAP_NP_C0402_DISCRETE_1UF" C0402#1 1465,2290 r90 top
C186 "CAP_NP_C0402_DISCRETE_0.1UF" C0402#1 1445,2370 r0 top
C187 "CAP_NP_C0402_DISCRETE_1UF" C0402#2 1755,2925 r0 bottom
C188 "CAP_NP_C0603_DISCRETE_100PF" C0603 1565,2320 r0 top
C189 "CAP_EC6P3_220UF" EC6P3 930,2375 r180 top
C190 "CAP_EC6P3_220UF" EC6P3 1200,2375 r180 top
C191 "CAP_NP_C0402_DISCRETE_0.1UF" C0402#1 1280,2465 r90 bottom
C192 "CAP_NP_C0402_DISCRETE_0.1UF" C0402#1 125,1550 r270 top
C431 "CAP_NP_C0603_DISCRETE_10UF" C0603 3350,330 r90 top
CN1 "WIFI_ANT_UFL-3_WIFI-ANT" UFL-3 4125,395 r180 top
D1 "DIODE BI-DIR TRIG_SMA214-CA_SMA" SMA214-CA 385,2450 r0 top
D2 "DIODE_SOD-123_1N4148W" SOD-123 920,2470 r0 bottom
D6 "BAT54C_SOT23_BAT54C" SOT23#1 480,2560 r0 bottom
D7 "DIODE BI-DIR TRIG_ES0402_KLXES1" ES0402#1 480,2730 r0 bottom
D8 "DIODE BI-DIR TRIG_SMB-CA_SMBJ15" SMB-CA 1120,720 r270 bottom
D9 "DIODE BI-DIR TRIG_SMB-CA_SMBJ15" SMB-CA 820,720 r270 bottom
D10 "DIODE BI-DIR TRIG_SMB-CA_SMBJ15" SMB-CA 970,720 r270 bottom
D11 "DIODE BI-DIR TRIG_SMB-CA_SMBJ15" SMB-CA 425,720 r270 bottom
D12 "DIODE BI-DIR TRIG_ES0402_KLXES1" ES0402#1 4685,580 r0 bottom
D13 "DIODE BI-DIR TRIG_ES0402_KLXES1" ES0402#1 4685,625 r0 bottom
D14 "DIODE BI-DIR TRIG_ES0402_KLXES1" ES0402#1 4685,670 r0 bottom
D15 "DIODE BI-DIR TRIG_ES0402_KLXES1" ES0402#1 4685,770 r0 bottom
D16 "DIODE BI-DIR TRIG_ES0402_KLXES1" ES0402#1 4685,815 r0 bottom
D17 "DIODE BI-DIR TRIG_ES0402_KLXES1" ES0402#1 4685,860 r0 bottom
D18 "DIODE BI-DIR TRIG_ES0402_KLXES1" ES0402#1 4685,905 r0 bottom
D19 "DIODE_SCHTKY_SOD523_IC_RB521S-3" SOD523 2511.22,940 r270 bottom
D20 "DIODE_SCHTKY_SOD523_IC_RB521S-3" SOD523 1956.22,940 r270 bottom
D21 "DIODE BI-DIR TRIG_SMB-CA_SMBJ6." SMB-CA 2371.22,720 r270 bottom
D22 "DIODE BI-DIR TRIG_SMB-CA_SMBJ6." SMB-CA 1846.22,720 r270 bottom
D23 "DIODE BI-DIR TRIG_SMB-CA_SMBJ6." SMB-CA 2221.22,720 r270 bottom
D24 "DIODE BI-DIR TRIG_SMB-CA_SMBJ6." SMB-CA 1696.22,720 r270 bottom
D26 "BAT54A_SOT23_BAT54A" SOT23#1 1065,2930 r0 bottom
D27 "DIODE_SCHTKY_SOD-123_IC_1N5819W" SOD-123 2355,2260 r0 top
D28 "DIODE BI-DIR TRIG_ES0402_KLXES1" ES0402#1 2704.18,2360 r0 top
D29 "DIODE BI-DIR TRIG_ES0402_KLXES1" ES0402#1 2704.18,2410 r0 top
D30 "DIODE BI-DIR TRIG_ES0402_KLXES1" ES0402#1 2704.18,2310 r0 top
D31 "DIODE BI-DIR TRIG_ES0402_KLXES1" ES0402#1 2704.18,2260 r0 top
D32 "DIODE BI-DIR TRIG_ES0402_KLXES1" ES0402#2 2505,2315 r0 bottom
D33 "DIODE BI-DIR TRIG_ES0402_KLXES1" ES0402#2 1140,3080 r0 bottom
D34 "DIODE BI-DIR TRIG_ES0402_KLXES1" ES0402#1 1060,3080 r0 bottom
D35 "DIODE BI-DIR TRIG_ES0402_KLXES1" ES0402#1 3915,2055 r180 top
D36 "DIODE BI-DIR TRIG_ES0402_KLXES1" ES0402#1 3835,2055 r0 top
D47 "DIODE BI-DIR TRIG_ES0402_KLXES1" ES0402#1 3455,330 r270 top
D48 "DIODE BI-DIR TRIG_ES0402_KLXES1" ES0402#1 3405,330 r270 top
D49 "DIODE BI-DIR TRIG_ES0402_KLXES1" ES0402#1 3145,315 r180 top
D50 "DIODE BI-DIR TRIG_ES0402_KLXES1" ES0402#1 3065,315 r0 top
D51 "DIODE BI-DIR TRIG_ES0402_KLXES1" ES0402#1 3945,385 r270 top
D52 "DIODE BI-DIR TRIG_ES0402_KLXES1" ES0402#1 3865,385 r270 top
D53 "DIODE BI-DIR TRIG_ES0402_KLXES1" ES0402#1 4415,300 r270 bottom
D54 "DIODE BI-DIR TRIG_ES0402_KLXES1" ES0402#1 4335,300 r270 bottom
F1 "FUSE_F1812_SMD1812P200TF16" F1812 385,2655 r0 top
H1 "SPACER_NPTH_M3_IC_NPTH_M3" NPTH_M3 158,3069.16 r0 top
H2 "SPACER_NPTH_M3_IC_NPTH_M3" NPTH_M3 5235.69,3069.16 r0 top
H3 "SPACER_NPTH_M3_IC_NPTH_M3" NPTH_M3 158,158 r0 top
H4 "SPACER_NPTH_M3_IC_NPTH_M3" NPTH_M3 5235.7,158 r0 top
J1 "DC-044A-20A_DC_IN_TH_3P_10R1X11" DC_IN_TH_3P_10R1X11R6 570.9,3035.03 r270 top
J2 "A1501WV-2P_ZH1P5MM_TH_2P_A1501W" ZH1P5MM_TH_2P 920.52,2665.52 r180 top
J3 "1X6PIN_PH-1X6-2P0_PH-6A" PH-1X6-2P0#1 122.36,1208.43 r270 top
J5 "1X2PIN_HDR1X2-2R54-TM-VM_NC" HDR1X2-2R54-TM-VM#1 980,925 r0 bottom
J6 "CON4_XH2P54-4P_XH-4A" XH2P54-4P 140,616.54 r90 top
J7 "1.25T-2A_GH1P25_TH_2P_1.25T-2A" GH1P25_TH_2P 689.02,2659.4 r0 top
J8 "CON6_DB2ERC-3P81-6P_CON6" DB2ERC-3P81-6P 866.66,182.38 r180 top
J9 "TF_CARD_TFCARD_IO_TF_CARD" TFCARD 5029.24,650 r270 bottom
J10 "1X2PIN_HDR1X2-2R54-TM-VM_HDR1X2" HDR1X2-2R54-TM-VM#2 2740,315 r0 top
J11 "1X2PIN_HDR1X2-2R54-TM-VM_HDR1X2" HDR1X2-2R54-TM-VM#2 2380,315 r0 top
J12 "CON4_DB2ERC-3P81-4P_WJ15EDGRC-3" DB2ERC-3P81-4P 1811.54,182.38 r180 top
J14 "HY911130A_HY911130A_HY911130A" HY911130A 2982.93,2873.58 r0 top
J15 "USB3D0_USB2D0-A-D_USB3D0-AF-18P" USB3D0-AF-18P 3686.28,2963.35 r180 top
J16 "TYPE-C-31-M-12_TYPE-C-31-M-12_T" TYPE-C-31-M-12 1075.93,3092.82 r180 top
J17 "USB-A-D_USB-A-D_USB-A-D" USB-A-D 4437.07,2949.36 r0 top
J18 "FPC-30P_FPC-30P-0P5_FPC_0R5_30P" FPC-30P-0P5 5225.05,2495 r90 top
J19 "FPC-30P_FPC-30P-0P5_FPC_0R5_30P" FPC-30P-0P5 5225.05,1625 r90 top
J20 "FPC-24P_FPC_24P_0P5_FPC_0P5_24P" FPC_24P_0P5 5241.8,2575 r90 bottom
J21 "FPC-24P_FPC_24P_0P5_FPC_0P5_24P" FPC_24P_0P5 5241.8,1915 r90 bottom
J22 "FPC-30P_FPC-30P-0P5_FPC_0R5_30P" FPC-30P-0P5 5225.05,755 r90 top
J23 "1X6PIN_PH-1X6-2P0_PH-6A" PH-1X6-2P0#2 2559.57,128.63 r0 top
J24 "MINI-PCIE_PCIE_52P_MINI-PCIE" PCIE_52P 4102.42,2329.46 r180 top
J25 "MIC_JACK_EAR_JACK_PJ-325C5-G" EAR_JACK 1467.92,2864.88 r270 top
J26 "MIC_JACK_EAR_JACK_PJ-325C5-R" EAR_JACK 1878.14,2864.88 r270 top
J27 "1X2PIN_HDR1X2-2R54-TM-VM_HDR1X2" HDR1X2-2R54-TM-VM#2 1565,2455 r180 top
J29 "1X2PIN_PH-1X2-2P0_L_PH" PH-1X2-2P0_L 1171.85,2692.91 r0 top
J30 "AS0A826-H2SB-7H_AS0A826-H2SB-7H" AS0A826-H2SB-7H 1853.82,1660.16 r180 top
J32 "1X4PIN_PH-1X4-2P0_PH-4A" PH-1X4-2P0 3110.75,128.63 r0 top
J34 "1X4PIN_PH-1X4-2P0_PH-4A" PH-1X4-2P0 3583.19,128.63 r0 top
J35 "1X4PIN_PH-1X4-2P0_PH-4A" PH-1X4-2P0 4055.63,128.63 r0 top
J36 "1X4PIN_PH-1X4-2P0_PH-4A" PH-1X4-2P0 4528.07,128.63 r0 top
L1 "IND_L4520_DISCRETE_3.3UH" L4520 135,1605 r270 bottom
L2 "IND_L4520_DISCRETE_3.3UH" L4520 405,1605 r270 bottom
L3 "IND_L4520_DISCRETE_3.3UH" L4520 395,2285 r0 bottom
L4 "IND_L2520_DISCRETE_2.2UH" L2520 2745,1305 r0 bottom
L5 "BEAD_L0603_DISCRETE_100R 100MHZ" L0603#1 2840,1110 r0 bottom
L6 "BEAD_L0603_DISCRETE_100R 100MHZ" L0603#2 2265,1210 r0 bottom
L7 "BEAD_L0603_DISCRETE_100R 100MHZ" L0603#1 3015,1585 r0 bottom
L8 "BEAD_L0603_DISCRETE_120R 100MHZ" L0603#1 830,2870 r270 top
L9 "BEAD_L0603_DISCRETE_330R 100MHZ" L0603#1 2545,3130 r90 bottom
L10 "IND_L4520_DISCRETE_3.3UH" L4520 4245,1390 r0 bottom
LED1 "LED_LED0603_BLUE" LED0603 5015,284.99 r90 top
LED2 "LED_LED0603_BLUE" LED0603 4915,284.99 r90 top
LED3 "LED_LED0603_BLUE" LED0603 4815,284.99 r90 top
LED4 "LED_LED0603_RED" LED0603 295,1655 r270 top
MARK "ID" MARK#1 905,3421 r0 bottom
MARK "ID" MARK#2 960,-180 r0 bottom
MARK "ID" MARK#3 4430,3415 r0 bottom
MARK "ID" MARK#4 4476,-195 r0 bottom
MARK "ID" MARK#5 4475,-195 r0 top
MARK "ID" MARK#6 960,-180 r0 top
MARK "ID" MARK#7 4430,3415 r0 top
MARK "ID" MARK#8 905,3420 r0 top
Q1 "MOSFET_P_SOT23_IC_AO3407" SOT23#2 920,2350 r0 bottom
Q2 "NPN_SOT23_IC_SS8050" SOT23#2 920,2180 r0 bottom
Q3 "NPN_SOT23_IC_SS8050" SOT23#2 265,2095 r0 bottom
Q4 "MOSFET_P_SOT23_IC_AO3407" SOT23#1 710,1420 r270 bottom
Q5 "MOSFET_P_SOT23_IC_AO3407" SOT23#1 425,1420 r270 bottom
Q6 "NPN_SOT23_IC_SS8050" SOT23#1 710,1275 r270 bottom
Q7 "MOSFET_P_SOT23_IC_AO3407" SOT23#1 3600,1055 r0 top
Q9 "2SK3018_SOT23_IC_2SK3018" SOT23#1 3240,2370 r180 top
Q10 "2SK3018_SOT23_IC_2SK3018" SOT23#1 3035,2370 r180 top
Q11 "2SK3018_SOT23_IC_2SK3018" SOT23#1 2840,2370 r180 top
Q12 "MOSFET_P_SOT23_IC_AO3407" SOT23#1 4850,1015 r270 top
Q13 "MOSFET_P_SOT23_IC_AO3407" SOT23#1 4850,890 r270 top
Q14 "NPN_SOT23_IC_SS8050" SOT23#1 4850,765 r270 top
R1 "RES_R0402_DISCRETE_1K" R0402#1 570,948.42 r0 bottom
R2 "RES_R0402_DISCRETE_3.4K" R0402#1 285,1025 r0 bottom
R3 "RES_R0402_DISCRETE_1K" R0402#2 760,1825 r270 bottom
R4 "RES_R0402_DISCRETE_100K" R0402#1 265,1840 r0 bottom
R5 "RES_R0402_DISCRETE_6.8K" R0402#2 675,1555 r270 bottom
R6 "RES_R0402_DISCRETE_30K" R0402#2 265,1880 r0 bottom
R7 "RES_R0402_DISCRETE_140K" R0402#2 285,1895 r270 top
R8 "RES_R0402_DISCRETE_20K" R0402#2 245,1895 r90 top
R9 "RES_R0603_DISCRETE_NC" R0603#1 1080,2160 r90 bottom
R10 "RES_R0603_DISCRETE_0R" R0603#1 1020,2160 r90 bottom
R11 "RES_R0402_DISCRETE_115K" R0402#1 540,1845 r0 bottom
R12 "RES_R0402_DISCRETE_20K" R0402#2 920,2265 r0 bottom
R13 "RES_R0402_DISCRETE_20K" R0402#2 540,1885 r0 bottom
R14 "RES_R0402_DISCRETE_140K" R0402#2 345,1915 r0 top
R15 "RES_R0402_DISCRETE_20K" R0402#2 345,1875 r180 top
R16 "RES_R0402_DISCRETE_4.7K" R0402#2 295,1765 r270 top
R17 "RES_R0402_DISCRETE_1K" R0402#2 955,2070 r90 bottom
R18 "RES_R0402_DISCRETE_10K" R0402#2 890,2070 r270 bottom
R19 "RES_R0402_DISCRETE_1K" R0402#2 265,1965 r0 bottom
R20 "RES_R0402_DISCRETE_115K" R0402#2 140,2420 r270 bottom
R21 "RES_R0402_DISCRETE_10K" R0402#1 265,2005 r0 bottom
R22 "RES_R0402_DISCRETE_20K" R0402#2 100,2420 r90 bottom
R23 "RES_R0402_DISCRETE_NC" R0402#2 85,2245 r90 top
R24 "RES_R0402_DISCRETE_1K" R0402#2 205,2245 r90 top
R25 "RES_R0402_DISCRETE_NC" R0402#2 125,2245 r270 top
R26 "RES_R0603_DISCRETE_0R" R0603#2 570,1380 r0 bottom
R27 "RES_R0402_DISCRETE_20K" R0402#1 830,1380 r0 bottom
R29 "RES_R0402_DISCRETE_510R" R0402#1 830,1240 r0 bottom
R30 "RES_R0402_DISCRETE_10K" R0402#2 830,1312.5 r0 bottom
R31 "RES_R0402_DISCRETE_1K" R0402#1 570,1098.42 r0 bottom
R32 "RES_R0402_DISCRETE_6.8K" R0402#1 285,1175 r0 bottom
R33 "RES_R0402_DISCRETE_1K" R0402#1 570,1250 r0 bottom
R34 "RES_R0402_DISCRETE_6.8K" R0402#1 285,1325 r0 bottom
R35 "RES_R0402_DISCRETE_25.5K" R0402#2 1085,1470 r90 top
R36 "RES_R0402_DISCRETE_10K" R0402#2 1085,1565 r270 top
R37 "RES_R0402_DISCRETE_10K" R0402#2 1230,1090 r270 bottom
R38 "RES_R0402_DISCRETE_10K" R0402#2 750,1070 r90 bottom
R39 "RES_R0402_DISCRETE_10K" R0402#2 255,400 r90 bottom
R40 "RES_R0402_DISCRETE_560R" R0402#2 275,570 r0 bottom
R41 "RES_R0402_DISCRETE_560R" R0402#2 275,705 r0 bottom
R42 "RES_R0402_DISCRETE_10K" R0402#1 175,900 r0 bottom
R43 "RES_R0402_DISCRETE_100R" R0402#2 165,1895 r270 top
R44 "RES_R0402_DISCRETE_10K" R0402#1 4960,125 r0 bottom
R45 "RES_R0402_DISCRETE_470R" R0402#2 5015,410 r90 top
R46 "RES_R0402_DISCRETE_22R" R0402#1 4960,165 r0 bottom
R47 "RES_R0402_DISCRETE_22R" R0402#1 4855,205 r0 bottom
R48 "RES_R0402_DISCRETE_470R" R0402#2 4915,410 r90 top
R49 "RES_R0402_DISCRETE_470R" R0402#2 4815,410 r90 top
R50 "RES_R0402_DISCRETE_0R" R0402#2 460,2670 r90 bottom
R51 "RES_R0402_DISCRETE_NC" R0402#2 500,2670 r270 bottom
R52 "RES_R0402_DISCRETE_10K" R0402#2 1235,940 r270 bottom
R53 "RES_R0402_DISCRETE_10K" R0402#2 1285,940 r270 bottom
R54 "RES_R0402_DISCRETE_10K" R0402#2 1385,940 r270 bottom
R55 "RES_R0402_DISCRETE_10K" R0402#2 1335,940 r270 bottom
R56 "RES_R0603_DISCRETE_0R" R0603#1 1120,510 r270 bottom
R57 "RES_R0603_DISCRETE_0R" R0603#1 970,510 r270 bottom
R58 "RES_R0603_DISCRETE_0R" R0603#1 820,510 r270 bottom
R59 "RES_R0603_DISCRETE_0R" R0603#1 425,510 r270 bottom
R60 "RES_R0402_DISCRETE_22R" R0402#2 4585,580 r0 bottom
R61 "RES_R0402_DISCRETE_22R" R0402#2 4585,625 r0 bottom
R62 "RES_R0402_DISCRETE_22R" R0402#2 4585,670 r0 bottom
R63 "RES_R0402_DISCRETE_22R" R0402#2 4585,770 r0 bottom
R64 "RES_R0402_DISCRETE_22R" R0402#2 4585,815 r0 bottom
R65 "RES_R0402_DISCRETE_22R" R0402#2 4585,860 r0 bottom
R66 "RES_R0402_DISCRETE_0R" R0402#2 4585,905 r0 bottom
R67 "RES_R0402_DISCRETE_10K" R0402#2 2511.22,520 r90 bottom
R68 "RES_R0402_DISCRETE_10K" R0402#2 1956.22,520 r90 bottom
R69 "RES_R0402_DISCRETE_10K" R0402#2 2661.22,520 r90 bottom
R70 "RES_R0402_DISCRETE_10K" R0402#2 2106.22,520 r90 bottom
R71 "RES_R0402_DISCRETE_4.7K" R0402#2 2561.22,940 r270 bottom
R72 "RES_R0402_DISCRETE_4.7K" R0402#2 2006.22,940 r270 bottom
R73 "RES_R0603_DISCRETE_120R" R0603#1 2745,400 r0 top
R74 "RES_R0603_DISCRETE_120R" R0603#1 2385,405 r0 top
R75 "RES_R0402_DISCRETE_10K" R0402#2 2611.22,520 r270 bottom
R76 "RES_R0402_DISCRETE_4.7K" R0402#2 2611.22,940 r90 bottom
R77 "RES_R0402_DISCRETE_10K" R0402#2 2056.22,520 r270 bottom
R78 "RES_R0402_DISCRETE_4.7K" R0402#2 2056.22,940 r90 bottom
R79 "RES_R0603_DISCRETE_0R" R0603#1 2371.22,510 r270 bottom
R80 "RES_R0603_DISCRETE_0R" R0603#1 2221.22,510 r270 bottom
R81 "RES_R0603_DISCRETE_0R" R0603#1 1846.22,510 r270 bottom
R82 "RES_R0603_DISCRETE_0R" R0603#1 1696.22,510 r270 bottom
R89 "RES_R0402_DISCRETE_NC" R0402#2 2910,1225 r0 bottom
R90 "RES_R0402_DISCRETE_NC" R0402#1 2910,1510 r0 bottom
R91 "RES_R0402_DISCRETE_0R" R0402#2 2910,1470 r0 bottom
R92 "RES_R0402_DISCRETE_0R" R0402#2 2910,1265 r0 bottom
R93 "RES_R0402_DISCRETE_4.7K" R0402#1 2810,1470 r0 bottom
R94 "RES_R0402_DISCRETE_4.7K" R0402#1 2810,1510 r0 bottom
R95 "RES_R0402_DISCRETE_4.7K" R0402#1 2810,1390 r0 bottom
R96 "RES_R0402_DISCRETE_22R" R0402#1 2710,1470 r0 bottom
R97 "RES_R0402_DISCRETE_22R" R0402#1 2710,1510 r0 bottom
R98 "RES_R0402_DISCRETE_2.49K" R0402#2 2385,1205 r270 bottom
R99 "RES_R0402_DISCRETE_22R" R0402#1 2710,1550 r0 bottom
R100 "RES_R0402_DISCRETE_22R" R0402#1 2710,1590 r0 bottom
R101 "RES_R0402_DISCRETE_22R" R0402#1 2710,1390 r0 bottom
R102 "RES_R0402_DISCRETE_22R" R0402#1 2710,1430 r0 bottom
R103 "RES_R0402_DISCRETE_4.7K" R0402#2 2810,1550 r0 bottom
R104 "RES_R0402_DISCRETE_4.7K" R0402#2 2810,1590 r0 bottom
R105 "RES_R0402_DISCRETE_4.7K" R0402#2 2810,1430 r0 bottom
R106 "RES_R0402_DISCRETE_NC" R0402#1 2550,1675 r0 bottom
R107 "RES_R0402_DISCRETE_0R" R0402#2 2550,1715 r0 bottom
R108 "RES_R0402_DISCRETE_4.7K" R0402#2 2450,1695 r270 bottom
R109 "RES_R0402_DISCRETE_4.7K" R0402#2 2490,1695 r270 bottom
R110 "RES_R0402_DISCRETE_4.7K" R0402#2 2620,1205 r90 bottom
R111 "RES_R0402_DISCRETE_510R" R0402#2 3005,3115 r90 bottom
R112 "RES_R0402_DISCRETE_NC" R0402#2 2620,1110 r90 bottom
R113 "RES_R0402_DISCRETE_0R" R0402#2 2465,1295 r0 top
R114 "RES_R0402_DISCRETE_510R" R0402#2 2965,3115 r90 bottom
R115 "RES_R0402_DISCRETE_NC" R0402#2 2465,1335 r0 top
R116 "RES_R0402_DISCRETE_4.7K" R0402#2 2570,1205 r270 bottom
R117 "RES_R0402_DISCRETE_4.7K" R0402#2 2530,1205 r270 bottom
R118 "RES_R0402_DISCRETE_4.7K" R0402#2 2570,1110 r270 bottom
R119 "RES_R0402_DISCRETE_NC" R0402#2 2390,1715 r0 bottom
R120 "RES_R0402_DISCRETE_10K" R0402#2 2390,1675 r0 bottom
R121 "RES_R0402_DISCRETE_0R" R0402#2 2530,1210 r270 top
R122 "RES_R0402_DISCRETE_NC" R0402#2 2530,1110 r270 top
R123 "RES_R0402_DISCRETE_0R" R0402#2 2715,1205 r90 bottom
R124 "RES_R0402_DISCRETE_0R" R0402#2 2675,1205 r270 bottom
R125 "RES_R0402_DISCRETE_2.2R" R0402#2 3730,920 r0 top
R126 "RES_R0402_DISCRETE_2.2R" R0402#2 3730,960 r0 top
R127 "RES_R0402_DISCRETE_10K" R0402#2 3600,919.44 r180 top
R128 "RES_R0402_DISCRETE_510R" R0402#2 3600,879.44 r180 top
R130 "RES_R0402_DISCRETE_2.2R" R0402#2 3550,3110 r90 bottom
R131 "RES_R0402_DISCRETE_2.2R" R0402#2 3590,3110 r90 bottom
R132 "RES_R0402_DISCRETE_2.2R" R0402#2 4495,3075 r90 bottom
R133 "RES_R0402_DISCRETE_2.2R" R0402#2 4455,3075 r90 bottom
R134 "RES_R0402_DISCRETE_2.2R" R0402#2 1119,3140 r90 bottom
R135 "RES_R0402_DISCRETE_2.2R" R0402#2 1079,3140 r90 bottom
R136 "RES_R0402_DISCRETE_2.2R" R0402#2 3726,3110 r90 bottom
R137 "RES_R0402_DISCRETE_2.2R" R0402#2 3689,3110 r90 bottom
R138 "RES_R0402_DISCRETE_100R" R0402#2 1065,2835 r0 bottom
R139 "RES_R0402_DISCRETE_2.2R" R0402#2 4415,3075 r90 bottom
R140 "RES_R0402_DISCRETE_2.2R" R0402#2 4375,3075 r90 bottom
R141 "RES_R0402_DISCRETE_1K" R0402#1 4920,3060 r0 bottom
R142 "RES_R0402_DISCRETE_2.2R" R0402#2 4940,3110 r90 top
R143 "RES_R0402_DISCRETE_2.2R" R0402#2 4980,3110 r90 top
R144 "RES_R0402_DISCRETE_3.4K" R0402#2 4670,3155 r90 bottom
R145 "RES_R0402_DISCRETE_100K" R0402#2 4900,3110 r270 top
R146 "RES_R0402_DISCRETE_100K" R0402#2 4860,3110 r270 top
R147 "RES_R0402_DISCRETE_1K" R0402#2 4335,3075 r90 bottom
R148 "RES_R0402_DISCRETE_3.4K" R0402#2 4175,3180 r0 bottom
R149 "RES_R0402_DISCRETE_10K" R0402#2 1510,1565 r90 top
R150 "RES_R0402_DISCRETE_1K" R0402#1 730,2185 r0 bottom
R151 "RES_R0402_DISCRETE_15K" R0402#2 1510,1660 r270 top
R152 "RES_R0603_DISCRETE_0R" R0603#1 5010,2890 r90 bottom
R153 "RES_R0402_DISCRETE_6.8K" R0402#1 730,2265 r0 bottom
R154 "RES_R0402_DISCRETE_1K" R0402#2 2705,2395 r0 bottom
R155 "RES_R0402_DISCRETE_100K" R0402#1 2705,2355 r0 bottom
R156 "RES_R0402_DISCRETE_27K" R0402#1 3235,2400 r0 bottom
R157 "RES_R0402_DISCRETE_10K" R0402#1 3040,2395 r0 bottom
R158 "RES_R0402_DISCRETE_2.2K" R0402#2 3140,2370 r270 top
R159 "RES_R0402_DISCRETE_10K" R0402#1 2845,2395 r0 bottom
R160 "RES_R0402_DISCRETE_2.2K" R0402#2 2935,2370 r270 top
R161 "RES_R0402_DISCRETE_0R" R0402#2 5060,2235 r0 bottom
R162 "RES_R0402_DISCRETE_0R" R0402#2 4987,1615 r0 top
R163 "RES_R0402_DISCRETE_10K" R0402#2 4987,2435 r0 top
R164 "RES_R0402_DISCRETE_10K" R0402#2 4987,2355 r0 top
R165 "RES_R0402_DISCRETE_10K" R0402#2 4845,1615 r0 top
R166 "RES_R0402_DISCRETE_10K" R0402#2 4987,1485 r0 top
R167 "RES_R0402_DISCRETE_10K" R0402#1 5060,2275 r0 bottom
R168 "RES_R0402_DISCRETE_10K" R0402#2 4987,2395 r0 top
R169 "RES_R0402_DISCRETE_10K" R0402#2 4987,1570 r0 top
R170 "RES_R0402_DISCRETE_10K" R0402#2 4987,1525 r0 top
R171 "RES_R0402_DISCRETE_1K" R0402#2 4845,1570 r180 top
R172 "RES_R0402_DISCRETE_1K" R0402#2 4705,2190 r0 bottom
R173 "RES_R0402_DISCRETE_6.8K" R0402#2 4988,1324 r0 top
R174 "RES_R0402_DISCRETE_6.8K" R0402#2 4988,2194 r0 top
R175 "RES_R0402_DISCRETE_6.8K" R0402#2 4987,2315 r0 top
R176 "RES_R0402_DISCRETE_6.8K" R0402#2 4987,1445 r0 top
R177 "RES_R0402_DISCRETE_NC" R0402#2 4885,2540 r90 bottom
R178 "RES_R0402_DISCRETE_0R" R0402#2 4885,2500 r270 bottom
R179 "RES_R0402_DISCRETE_NC" R0402#2 4845,2540 r90 bottom
R180 "RES_R0402_DISCRETE_1K" R0402#2 4645,2017.4 r0 top
R181 "RES_R0402_DISCRETE_0R" R0402#2 4845,2500 r270 bottom
R182 "RES_R0402_DISCRETE_6.8K" R0402#2 4988,2064 r0 top
R183 "RES_R0402_DISCRETE_NC" R0402#2 4805,2540 r90 bottom
R184 "RES_R0402_DISCRETE_0R" R0402#2 4805,2500 r270 bottom
R185 "RES_R0402_DISCRETE_NC" R0402#2 4765,2540 r90 bottom
R186 "RES_R0402_DISCRETE_0R" R0402#2 4765,2500 r270 bottom
R187 "RES_R0402_DISCRETE_1K" R0402#2 4640,1147.4 r0 top
R188 "RES_R0402_DISCRETE_6.8K" R0402#2 4988,1194 r0 top
R189 "RES_R0402_DISCRETE_NC" R0402#2 4988,575 r0 top
R190 "RES_R0402_DISCRETE_10K" R0402#2 2540,305 r270 top
R191 "RES_R0402_DISCRETE_10K" R0402#2 2580,305 r270 top
R192 "RES_R0402_DISCRETE_NC" R0402#2 4988,695 r0 top
R193 "RES_R0402_DISCRETE_1K" R0402#2 2780,940 r270 bottom
R194 "RES_R0603_DISCRETE_0R" R0603#1 4740,890 r270 top
R195 "RES_R0402_DISCRETE_6.8K" R0402#2 2740,600 r270 bottom
R196 "RES_R0402_DISCRETE_20K" R0402#2 4988,735 r180 top
R198 "RES_R0402_DISCRETE_1K" R0402#2 4740,730 r0 top
R199 "RES_R0402_DISCRETE_10K" R0402#2 4740,805 r180 top
R200 "RES_R0402_DISCRETE_15K" R0402#2 4485,1055 r270 bottom
R201 "RES_R0402_DISCRETE_0R" R0402#2 4465,950 r0 bottom
R202 "RES_R0402_DISCRETE_0R" R0402#2 4565,1055 r270 bottom
R203 "RES_R0402_DISCRETE_100K" R0402#2 3997.6,1535 r270 bottom
R204 "RES_R0402_DISCRETE_0R" R0402#2 4445,1055 r270 bottom
R205 "RES_R0402_DISCRETE_30K" R0402#2 3957.6,1535 r90 bottom
R206 "RES_R0402_DISCRETE_1K" R0402#2 4077.6,1535 r270 bottom
R208 "RES_R0402_DISCRETE_4.7K" R0402#2 4552.5,2470 r270 bottom
R209 "RES_R0402_DISCRETE_22R" R0402#2 4512.5,2470 r270 bottom
R210 "RES_R0402_DISCRETE_22R" R0402#2 4472.5,2470 r270 bottom
R211 "RES_R0402_DISCRETE_100R" R0402#2 4145,1995 r270 top
R212 "RES_R0402_DISCRETE_100R" R0402#2 4105,1995 r270 top
R213 "RES_R0402_DISCRETE_2.2R" R0402#2 3895,1995 r270 top
R214 "RES_R0402_DISCRETE_2.2R" R0402#2 3855,1995 r270 top
R215 "RES_R0402_DISCRETE_120R" R0402#2 1425,2290 r270 top
R216 "RES_R0402_DISCRETE_2.2K" R0402#2 1525,2270 r0 top
R217 "RES_R0402_DISCRETE_10K" R0402#2 1320,2465 r90 bottom
R218 "RES_R0402_DISCRETE_22R" R0402#1 1755,2965 r0 bottom
R219 "RES_R0402_DISCRETE_0R" R0402#2 1755,3120 r90 bottom
R220 "RES_R0402_DISCRETE_2.2K" R0402#2 1605,2270 r0 top
R221 "RES_R0402_DISCRETE_0R" R0402#2 2125,3120 r90 bottom
R222 "RES_R0402_DISCRETE_510R" R0402#2 3065,355 r180 top
R223 "RES_R0402_DISCRETE_0R" R0402#2 1160,2460 r90 bottom
R224 "RES_R0402_DISCRETE_0R" R0402#2 1200,2460 r90 bottom
R225 "RES_R0402_DISCRETE_510R" R0402#2 3905,385 r90 top
R232 "RES_R0402_DISCRETE_100R" R0402#2 165,1550 r270 top
R233 "RES_R0402_DISCRETE_510R" R0402#2 3145,355 r0 top
R234 "RES_R0402_DISCRETE_510R" R0402#2 3825,385 r90 top
R235 "RES_R0402_DISCRETE_510R" R0402#2 4375,300 r90 bottom
R236 "RES_R0402_DISCRETE_510R" R0402#2 4295,300 r90 bottom
R237 "RES_R0402_DISCRETE_510R" R0402#2 3405,430 r90 top
R238 "RES_R0402_DISCRETE_510R" R0402#2 3455,430 r90 top
R239 "RES_R0402_DISCRETE_10K" R0402#2 205,1550 r270 top
SS1 "SPACER_T3R2-5R2_TOPSMT_IC_M2X3M" T3R2-5R2_TOPSMT 4578.79,437.78 r0 bottom
SS2 "SPACER_T3R2-5R2_TOPSMT_IC_M2X3M" T3R2-5R2_TOPSMT 3626.03,437.78 r0 bottom
SS5 "SPACER_SMTSO-M2R5_IC_M2.5X3MM" SMTSO-M2R5 3083.14,577.48 r0 top
SS6 "SPACER_SMTSO-M2R5_IC_M2.5X3MM" SMTSO-M2R5 618.58,577.48 r0 top
SW1 "SW_PB_ESW_SW4-4R20X3R25-SM_IC_S" SW4-4R20X3R25-SM 125.31,2774.71 r270 top
SW2 "SW_PB_ESW_SW4-4R20X3R25-SM_IC_S" SW4-4R20X3R25-SM 125.31,2419.71 r270 top
SW3 "SW_PB_ESW_SW4-4R20X3R25-SM_IC_S" SW4-4R20X3R25-SM 125.31,2064.71 r270 top
SW4 "SW_PB_ESW_SW4-4R20X3R25-SM_IC_S" SW4-4R20X3R25-SM 124.69,1710.29 r270 top
U1 "MT9700_SOT23-5_MT9700" SOT23-5#1 425,980 r90 bottom
U2 "MT9700_SOT23-5_MT9700" SOT23-5#2 720,1700 r0 bottom
U3 "TP6327GS6_SOT23_6_TP6327GS6" SOT23_6#1 130,1845 r90 bottom
U4 "TP6327GS6_SOT23_6_TP6327GS6" SOT23_6#1 400,1845 r90 bottom
U5 "TP6327GS6_SOT23_6_TP6327GS6" SOT23_6#2 135,2285 r0 bottom
U6 "MT9700_SOT23-5_MT9700" SOT23-5#1 425,1130 r90 bottom
U7 "MT9700_SOT23-5_MT9700" SOT23-5#1 425,1285 r90 bottom
U8 "W25QXX_8P_SOIC8-208_NC" SOIC8-208 980,1095 r0 bottom
U9 "74LVC1G125_SOT-353_74LVC1G125GW" SOT-353#1 305,500 r90 bottom
U10 "74LVC1G125_SOT-353_74LVC1G125GW" SOT-353#2 285,805 r0 bottom
U11 "IRM-V838M3-C/TR1_SMD4-6R80X2R50" SMD4-6R80X2R50 4915.52,101.7 r180 top
U12 "RX8010SJ_SOP8_RX8010SJ" SOP8#1 224.85,2605.07 r90 bottom
U13 "MAX3232CSE_SOIC16_MAX3232CSE" SOIC16 1410,720 r90 bottom
U14 "TJA1057GT3_SOP8_IC_MAX3485" SOP8#2 2586.22,711.07 r0 bottom
U15 "TJA1057GT3_SOP8_IC_MAX3485" SOP8#2 2031.22,711.07 r0 bottom
U16 "RTL8211F_QFP_40P_R_JL2101-N040C" QFP_40P_R 2475,1435 r0 bottom
U17 "RTL8723_RL-UM02WBS-8723BU_TL882" RL-UM02WBS-8723BU 4102.42,923.62 r180 top
U18 "RCLAMP0524P_USON_10_RCLAMP0524P" USON_10#1 3610,3025 r0 bottom
U19 "RCLAMP0524P_USON_10_RCLAMP0524P" USON_10#1 3750,3025 r0 bottom
U20 "RCLAMP0524P_USON_10_RCLAMP0524P" USON_10#1 4435,2970 r0 bottom
U21 "MT9700_SOT23-5_MT9700" SOT23-5#1 4790,3095 r90 bottom
U22 "CH334F_QFN24_CH334F" QFN24 4915,2920 r90 top
U24 "MT9700_SOT23-5_MT9700" SOT23-5#1 4175,3095 r90 bottom
U25 "MT9700_SOT23-5_MT9700" SOT23-5#1 730,2355 r270 bottom
U26 "HDMI-001C_HDMI-SMD_IO_HDMI-001C" HDMI-SMD 2414.86,2841.62 r90 top
U27 "RCLAMP0524P_USON_10_RCLAMP0524P" USON_10#2 2144,2657 r90 top
U28 "RCLAMP0524P_USON_10_RCLAMP0524P" USON_10#2 2144,2519 r90 top
U29 "MT9700_SOT23-5_MT9700" SOT23-5#1 4845,2150 r90 top
U30 "MT9700_SOT23-5_MT9700" SOT23-5#1 4845,1280 r90 top
U31 "MT9700_SOT23-5_MT9700" SOT23-5#1 4845,2340 r90 top
U32 "MT9700_SOT23-5_MT9700" SOT23-5#1 4845,1470 r90 top
U33 "MT9700_SOT23-5_MT9700" SOT23-5#1 4845,2020 r90 top
U34 "MT9700_SOT23-5_MT9700" SOT23-5#1 4845,1150 r90 top
U35 "MT9700_SOT23-5_MT9700" SOT23-5#2 2780,720 r0 bottom
U36 "TP6327GS6_SOT23_6_TP6327GS6" SOT23_6#2 3995,1395 r0 bottom
U37 "SIM-7-1_NANO_SIM_SIM-7-1" NANO_SIM 5094.48,1280 r270 bottom
U38 "NUP5120-D_SOT563_NUP5120X6T1G" SOT563 4680,985.06 r0 bottom
Y1 "CRYSTAL_4P_3225_IC_25MHZ" 3225 2455,1085 r0 bottom
Y2 "CRYSTAL_4P_3225_IC_12MHZ" 3225 4915,2655 r0 top
Z1 "DIODE BI-DIR TRIG_ES0402_KLXES1" ES0402#1 100,2620 r180 top
Z2 "DIODE BI-DIR TRIG_ES0402_KLXES1" ES0402#1 275,610 r0 bottom
Z3 "DIODE BI-DIR TRIG_ES0402_KLXES1" ES0402#1 275,665 r0 bottom
Z4 "DIODE BI-DIR TRIG_ES0402_KLXES1" ES0402#1 180,2580 r180 top
Z5 "DIODE BI-DIR TRIG_ES0402_KLXES1" ES0402#1 85,1895 r90 top
Z7 "DIODE BI-DIR TRIG_ES0402_KLXES1" ES0402#1 1525,2370 r0 top
Z8 "DIODE BI-DIR TRIG_ES0402_KLXES1" ES0402#1 1035,2535 r0 bottom
Z9 "DIODE BI-DIR TRIG_ES0402_KLXES1" ES0402#2 1125,2535 r0 bottom
Z10 "DIODE BI-DIR TRIG_ES0402_KLXES1" ES0402#1 1605,2370 r180 top
Z11 "DIODE BI-DIR TRIG_ES0402_KLXES1" ES0402#1 1140,2400 r0 bottom
Z13 "DIODE BI-DIR TRIG_ES0402_KLXES1" ES0402#2 1220,2400 r0 bottom
Z23 "DIODE BI-DIR TRIG_ES0402_KLXES1" ES0402#1 85,1550 r90 top

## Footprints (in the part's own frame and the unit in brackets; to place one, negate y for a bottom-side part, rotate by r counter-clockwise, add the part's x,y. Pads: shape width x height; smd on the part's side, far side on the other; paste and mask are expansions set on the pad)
3225 [mm] "3225"
  rect 1.3x1 smd: 1(-1.15,-0.75) 2(1.15,-0.75) 3(1.15,0.75) 4(-1.15,0.75)
  silkscreen extent -1.45,-1.95 0.3,1.2, body extent -1.9,-1.4 1.9,1.4, height 3.81
AS0A826-H2SB-7H [mm] "AS0A826-H2SB-7H"
  rect 0.3x2 smd: 1(-33.425,-12.1) 2(-33.175,-3.9) 3(-32.925,-12.1) 4(-32.675,-3.9) 5(-32.425,-12.1) 6(-32.175,-3.9) 7(-31.925,-12.1) 8(-31.675,-3.9) 9(-31.425,-12.1) 10(-31.175,-3.9) 11(-30.925,-12.1) 12(-30.675,-3.9) 13(-30.425,-12.1) 14(-30.175,-3.9) 15(-29.925,-12.1) 16(-29.675,-3.9) 17(-29.425,-12.1) 18(-29.175,-3.9) 19(-28.925,-12.1) 20(-28.675,-3.9) 21(-28.425,-12.1) 22(-28.175,-3.9) 23(-27.925,-12.1) 24(-27.675,-3.9) 25(-27.425,-12.1) 26(-27.175,-3.9) 27(-26.925,-12.1) 28(-26.675,-3.9) 29(-26.425,-12.1) 30(-26.175,-3.9) 31(-25.925,-12.1) 32(-25.675,-3.9) 33(-25.425,-12.1) 34(-25.175,-3.9) 35(-24.925,-12.1) 36(-24.675,-3.9) 37(-24.425,-12.1) 38(-24.175,-3.9) 39(-23.925,-12.1) 40(-23.675,-3.9) 41(-23.425,-12.1) 42(-23.175,-3.9) 43(-22.925,-12.1) 44(-22.675,-3.9) 45(-22.425,-12.1) 46(-22.175,-3.9) 47(-21.925,-12.1) 48(-21.675,-3.9) 49(-21.425,-12.1) 50(-21.175,-3.9) 51(-20.925,-12.1) 52(-20.675,-3.9) 53(-20.425,-12.1) 54(-20.175,-3.9) 55(-19.925,-12.1) 56(-19.675,-3.9) 57(-19.425,-12.1) 58(-19.175,-3.9) 59(-18.925,-12.1) 60(-18.675,-3.9) 61(-18.425,-12.1) 62(-18.175,-3.9) 63(-17.925,-12.1) 64(-17.675,-3.9) 65(-17.425,-12.1) 66(-17.175,-3.9) 67(-16.925,-12.1) 68(-16.675,-3.9) 69(-16.425,-12.1) 70(-16.175,-3.9) 71(-15.925,-12.1) 72(-15.675,-3.9) 73(-15.425,-12.1) 74(-15.175,-3.9) 75(-14.925,-12.1) 76(-14.675,-3.9) 77(-14.425,-12.1) 78(-14.175,-3.9) 79(-13.925,-12.1) 80(-13.675,-3.9) 81(-13.425,-12.1) 82(-13.175,-3.9) 83(-12.925,-12.1) 84(-12.675,-3.9) 85(-12.425,-12.1) 86(-12.175,-3.9) 87(-11.925,-12.1) 88(-11.675,-3.9) 89(-11.425,-12.1) 90(-11.175,-3.9) 91(-10.925,-12.1) 92(-10.675,-3.9) 93(-10.425,-12.1) 94(-10.175,-3.9) 95(-9.925,-12.1) 96(-9.675,-3.9) 97(-9.425,-12.1) 98(-9.175,-3.9) 99(-8.925,-12.1) 100(-8.675,-3.9) 101(-8.425,-12.1) 102(-8.175,-3.9) 103(-7.925,-12.1) 104(-7.675,-3.9) 105(-7.425,-12.1) 106(-7.175,-3.9) 107(-6.925,-12.1) 108(-6.675,-3.9) 109(-6.425,-12.1) 110(-6.175,-3.9) 111(-5.925,-12.1) 112(-5.675,-3.9) 113(-5.425,-12.1) 114(-5.175,-3.9) 115(-4.925,-12.1) 116(-4.675,-3.9) 117(-4.425,-12.1) 118(-4.175,-3.9) 119(-3.925,-12.1) 120(-3.675,-3.9) 121(-3.425,-12.1) 122(-3.175,-3.9) 123(-2.925,-12.1) 124(-2.675,-3.9) 125(-2.425,-12.1) 126(-2.175,-3.9) 127(-1.925,-12.1) 128(-1.675,-3.9) 129(-1.425,-12.1) 130(-1.175,-3.9) 131(-0.925,-12.1) 132(-0.675,-3.9) 133(-0.425,-12.1) 134(-0.175,-3.9) 135(0.075,-12.1) 136(0.325,-3.9) 137(0.575,-12.1) 138(0.825,-3.9) 139(1.075,-12.1) 140(1.325,-3.9) 141(1.575,-12.1) 142(1.825,-3.9) 143(2.075,-12.1) 144(2.325,-3.9) 145(4.575,-12.1) 146(4.825,-3.9) 147(5.075,-12.1) 148(5.325,-3.9) 149(5.575,-12.1) 150(5.825,-3.9) 151(6.075,-12.1) 152(6.325,-3.9) 153(6.575,-12.1) 154(6.825,-3.9) 155(7.075,-12.1) 156(7.325,-3.9) 157(7.575,-12.1) 158(7.825,-3.9) 159(8.075,-12.1) 160(8.325,-3.9) 161(8.575,-12.1) 162(8.825,-3.9) 163(9.075,-12.1) 164(9.325,-3.9) 165(9.575,-12.1) 166(9.825,-3.9) 167(10.075,-12.1) 168(10.325,-3.9) 169(10.575,-12.1) 170(10.825,-3.9) 171(11.075,-12.1) 172(11.325,-3.9) 173(11.575,-12.1) 174(11.825,-3.9) 175(12.075,-12.1) 176(12.325,-3.9) 177(12.575,-12.1) 178(12.825,-3.9) 179(13.075,-12.1) 180(13.325,-3.9) 181(13.575,-12.1) 182(13.825,-3.9) 183(14.075,-12.1) 184(14.325,-3.9) 185(14.575,-12.1) 186(14.825,-3.9) 187(15.075,-12.1) 188(15.325,-3.9) 189(15.575,-12.1) 190(15.825,-3.9) 191(16.075,-12.1) 192(16.325,-3.9) 193(16.575,-12.1) 194(16.825,-3.9) 195(17.075,-12.1) 196(17.325,-3.9) 197(17.575,-12.1) 198(17.825,-3.9) 199(18.075,-12.1) 200(18.325,-3.9) 201(18.575,-12.1) 202(18.825,-3.9) 203(19.075,-12.1) 204(19.325,-3.9) 205(19.575,-12.1) 206(19.825,-3.9) 207(20.075,-12.1) 208(20.325,-3.9) 209(20.575,-12.1) 210(20.825,-3.9) 211(21.075,-12.1) 212(21.325,-3.9) 213(21.575,-12.1) 214(21.825,-3.9) 215(22.075,-12.1) 216(22.325,-3.9) 217(22.575,-12.1) 218(22.825,-3.9) 219(23.075,-12.1) 220(23.325,-3.9) 221(23.575,-12.1) 222(23.825,-3.9) 223(24.075,-12.1) 224(24.325,-3.9) 225(24.575,-12.1) 226(24.825,-3.9) 227(25.075,-12.1) 228(25.325,-3.9) 229(25.575,-12.1) 230(25.825,-3.9) 231(26.075,-12.1) 232(26.325,-3.9) 233(26.575,-12.1) 234(26.825,-3.9) 235(27.075,-12.1) 236(27.325,-3.9) 237(27.575,-12.1) 238(27.825,-3.9) 239(28.075,-12.1) 240(28.325,-3.9) 241(28.575,-12.1) 242(28.825,-3.9) 243(29.075,-12.1) 244(29.325,-3.9) 245(29.575,-12.1) 246(29.825,-3.9) 247(30.075,-12.1) 248(30.325,-3.9) 249(30.575,-12.1) 250(30.825,-3.9) 251(31.075,-12.1) 252(31.325,-3.9) 253(31.575,-12.1) 254(31.825,-3.9) 255(32.075,-12.1) 256(32.325,-3.9) 257(32.575,-12.1) 258(32.825,-3.9) 259(33.075,-12.1) 260(33.325,-3.9)
  rect 4.5x4.6 smd: 261(-33.85,4) 262(33.75,4)
  round 1.7 hole 1.7 unplated: ""(-34.45,-8)
  round 1.2 hole 1.2 unplated: ""(34.15,-8)
  silkscreen extent -39.05,-14.09 38.95,13.1, body extent -39.05,-13.2 39.05,13.2, height 3.81
C0402#1 [mil] "C0402"
  rect 23.6x23.6 smd: 1(-19.68,0) 2(19.68,0)
  silkscreen extent -37,-17 37,17, body extent -37,-17 37,17, height 150
C0402#2 [mil] "C0402"
  rect 23.6x23.6 smd: 1(19.68,0) 2(-19.68,0)
  silkscreen extent -37,-17 37,17, body extent -37,-17 37,17, height 150
C0603 [mil] "C0603"
  rect 31.5x31.5 smd: 1(-31.5,0) 2(31.5,0)
  silkscreen extent -55,-25 55,25, body extent -48,-16 48,16, height 150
